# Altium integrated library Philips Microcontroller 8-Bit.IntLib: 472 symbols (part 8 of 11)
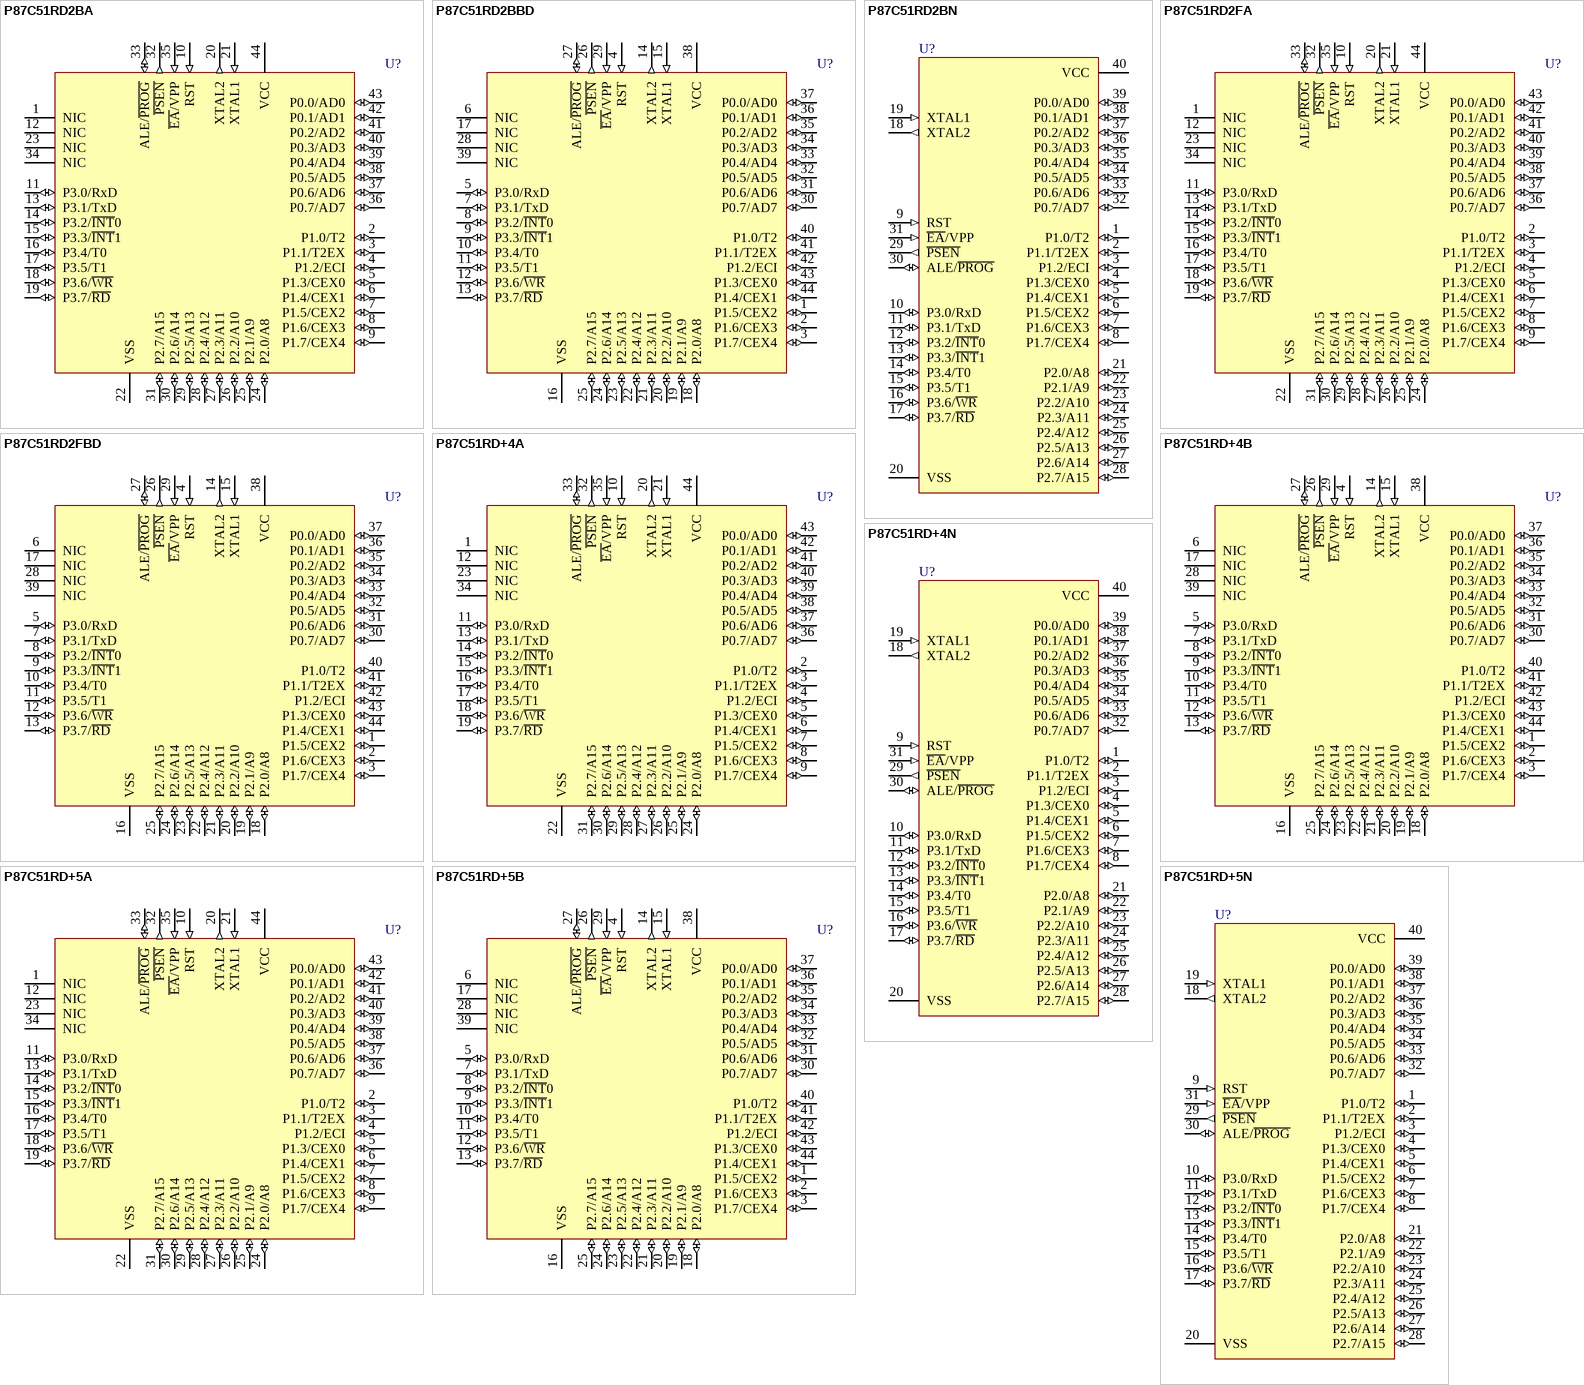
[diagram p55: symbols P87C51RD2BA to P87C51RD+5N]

## P87C51RD2FBD
designator U?
80C51 8-Bit Microcontroller Family: 64 kB OTP with 1 kB RAM, 2.7 to 5.5 V, Low Power, High Speed
footprint SOT389-1_N (Thin QFP, 44-Leads, Body 10x10mm, Pitch 0.8mm, IPC Medium Density)
footprint SOT389-1_L (Thin QFP, 44-Leads, Body 10x10mm, Pitch 0.8mm, IPC High Density)
footprint SOT389-1_M (Thin QFP, 44-Leads, Body 10x10mm, Pitch 0.8mm, IPC Low Density)
pins: 1 P1.5/CEX2 (io), 2 P1.6/CEX3 (io), 3 P1.7/CEX4 (io), 4 RST (in), 5 P3.0/RxD (io), 6 NIC, 7 P3.1/TxD (io), 8 P3.2/~{INT}0 (io), 9 P3.3/~{INT}1 (io), 10 P3.4/T0 (io), 11 P3.5/T1 (io), 12 P3.6/~{WR} (io), 13 P3.7/~{RD} (io), 14 XTAL2 (out), 15 XTAL1 (in), 16 VSS (power), 17 NIC, 18 P2.0/A8 (io), 19 P2.1/A9 (io), 20 P2.2/A10 (io), 21 P2.3/A11 (io), 22 P2.4/A12 (io), 23 P2.5/A13 (io), 24 P2.6/A14 (io), 25 P2.7/A15 (io), 26 ~{PSEN} (out), 27 ALE/~{PROG} (io), 28 NIC, 29 ~{EA}/VPP (in), 30 P0.7/AD7 (io), 31 P0.6/AD6 (io), 32 P0.5/AD5 (io), 33 P0.4/AD4 (io), 34 P0.3/AD3 (io), 35 P0.2/AD2 (io), 36 P0.1/AD1 (io), 37 P0.0/AD0 (io), 38 VCC (power), 39 NIC, 40 P1.0/T2 (io), 41 P1.1/T2EX (io), 42 P1.2/ECI (io), 43 P1.3/CEX0 (io), 44 P1.4/CEX1 (io)

## P87C51RD+4A
designator U?
80C51 8-Bit Microcontroller Family: 1 kB RAM, 64 kB OTP, 2.7V-5.5V, Low Power, High Speed
footprint SOT187-2_N (Leaded Chip Carrier, 44-Leads, Body 16.6x16.6mm, Pitch 1.27mm, IPC Medium Density)
footprint SOT187-2_L (Leaded Chip Carrier, 44-Leads, Body 16.6x16.6mm, Pitch 1.27mm, IPC High Density)
footprint SOT187-2_M (Leaded Chip Carrier, 44-Leads, Body 16.6x16.6mm, Pitch 1.27mm, IPC Low Density)
pins: 1 NIC, 2 P1.0/T2 (io), 3 P1.1/T2EX (io), 4 P1.2/ECI (io), 5 P1.3/CEX0 (io), 6 P1.4/CEX1 (io), 7 P1.5/CEX2 (io), 8 P1.6/CEX3 (io), 9 P1.7/CEX4 (io), 10 RST (in), 11 P3.0/RxD (io), 12 NIC, 13 P3.1/TxD (io), 14 P3.2/~{INT}0 (io), 15 P3.3/~{INT}1 (io), 16 P3.4/T0 (io), 17 P3.5/T1 (io), 18 P3.6/~{WR} (io), 19 P3.7/~{RD} (io), 20 XTAL2 (out), 21 XTAL1 (in), 22 VSS (power), 23 NIC, 24 P2.0/A8 (io), 25 P2.1/A9 (io), 26 P2.2/A10 (io), 27 P2.3/A11 (io), 28 P2.4/A12 (io), 29 P2.5/A13 (io), 30 P2.6/A14 (io), 31 P2.7/A15 (io), 32 ~{PSEN} (out), 33 ALE/~{PROG} (io), 34 NIC, 35 ~{EA}/VPP (in), 36 P0.7/AD7 (io), 37 P0.6/AD6 (io), 38 P0.5/AD5 (io), 39 P0.4/AD4 (io), 40 P0.3/AD3 (io), 41 P0.2/AD2 (io), 42 P0.1/AD1 (io), 43 P0.0/AD0 (io), 44 VCC (power)

## P87C51RD+4B
designator U?
80C51 8-Bit Microcontroller Family: 1 kB RAM, 64 kB OTP, 2.7V-5.5V, Low Power, High Speed
footprint SOT307-2_N (QFP, 44-Leads, Body 10x10mm, Pitch 0.8mm, IPC Medium Density)
footprint SOT307-2_L (QFP, 44-Leads, Body 10x10mm, Pitch 0.8mm, IPC High Density)
footprint SOT307-2_M (QFP, 44-Leads, Body 10x10mm, Pitch 0.8mm, IPC Low Density)
pins: 1 P1.5/CEX2 (io), 2 P1.6/CEX3 (io), 3 P1.7/CEX4 (io), 4 RST (in), 5 P3.0/RxD (io), 6 NIC, 7 P3.1/TxD (io), 8 P3.2/~{INT}0 (io), 9 P3.3/~{INT}1 (io), 10 P3.4/T0 (io), 11 P3.5/T1 (io), 12 P3.6/~{WR} (io), 13 P3.7/~{RD} (io), 14 XTAL2 (out), 15 XTAL1 (in), 16 VSS (power), 17 NIC, 18 P2.0/A8 (io), 19 P2.1/A9 (io), 20 P2.2/A10 (io), 21 P2.3/A11 (io), 22 P2.4/A12 (io), 23 P2.5/A13 (io), 24 P2.6/A14 (io), 25 P2.7/A15 (io), 26 ~{PSEN} (out), 27 ALE/~{PROG} (io), 28 NIC, 29 ~{EA}/VPP (in), 30 P0.7/AD7 (io), 31 P0.6/AD6 (io), 32 P0.5/AD5 (io), 33 P0.4/AD4 (io), 34 P0.3/AD3 (io), 35 P0.2/AD2 (io), 36 P0.1/AD1 (io), 37 P0.0/AD0 (io), 38 VCC (power), 39 NIC, 40 P1.0/T2 (io), 41 P1.1/T2EX (io), 42 P1.2/ECI (io), 43 P1.3/CEX0 (io), 44 P1.4/CEX1 (io)

## P87C51RD+4N
designator U?
80C51 8-Bit Microcontroller Family: 1 kB RAM, 64 kB OTP, 2.7V-5.5V, Low Power, High Speed
footprint SOT129-1 (DIP, Plastic; 40 Leads; Row Spacing 15.24 mm; Pitch 2.54 mm)
pins: 1 P1.0/T2 (io), 2 P1.1/T2EX (io), 3 P1.2/ECI (io), 4 P1.3/CEX0 (io), 5 P1.4/CEX1 (io), 6 P1.5/CEX2 (io), 7 P1.6/CEX3 (io), 8 P1.7/CEX4 (io), 9 RST (in), 10 P3.0/RxD (io), 11 P3.1/TxD (io), 12 P3.2/~{INT}0 (io), 13 P3.3/~{INT}1 (io), 14 P3.4/T0 (io), 15 P3.5/T1 (io), 16 P3.6/~{WR} (io), 17 P3.7/~{RD} (io), 18 XTAL2 (out), 19 XTAL1 (in), 20 VSS (power), 21 P2.0/A8 (io), 22 P2.1/A9 (io), 23 P2.2/A10 (io), 24 P2.3/A11 (io), 25 P2.4/A12 (io), 26 P2.5/A13 (io), 27 P2.6/A14 (io), 28 P2.7/A15 (io), 29 ~{PSEN} (out), 30 ALE/~{PROG} (io), 31 ~{EA}/VPP (in), 32 P0.7/AD7 (io), 33 P0.6/AD6 (io), 34 P0.5/AD5 (io), 35 P0.4/AD4 (io), 36 P0.3/AD3 (io), 37 P0.2/AD2 (io), 38 P0.1/AD1 (io), 39 P0.0/AD0 (io), 40 VCC (power)

## P87C51RD+5A
designator U?
80C51 8-Bit Microcontroller Family: 1 kB RAM, 64 kB OTP, 2.7V-5.5V, Low Power, High Speed
footprint SOT187-2_N (Leaded Chip Carrier, 44-Leads, Body 16.6x16.6mm, Pitch 1.27mm, IPC Medium Density)
footprint SOT187-2_L (Leaded Chip Carrier, 44-Leads, Body 16.6x16.6mm, Pitch 1.27mm, IPC High Density)
footprint SOT187-2_M (Leaded Chip Carrier, 44-Leads, Body 16.6x16.6mm, Pitch 1.27mm, IPC Low Density)
pins: 1 NIC, 2 P1.0/T2 (io), 3 P1.1/T2EX (io), 4 P1.2/ECI (io), 5 P1.3/CEX0 (io), 6 P1.4/CEX1 (io), 7 P1.5/CEX2 (io), 8 P1.6/CEX3 (io), 9 P1.7/CEX4 (io), 10 RST (in), 11 P3.0/RxD (io), 12 NIC, 13 P3.1/TxD (io), 14 P3.2/~{INT}0 (io), 15 P3.3/~{INT}1 (io), 16 P3.4/T0 (io), 17 P3.5/T1 (io), 18 P3.6/~{WR} (io), 19 P3.7/~{RD} (io), 20 XTAL2 (out), 21 XTAL1 (in), 22 VSS (power), 23 NIC, 24 P2.0/A8 (io), 25 P2.1/A9 (io), 26 P2.2/A10 (io), 27 P2.3/A11 (io), 28 P2.4/A12 (io), 29 P2.5/A13 (io), 30 P2.6/A14 (io), 31 P2.7/A15 (io), 32 ~{PSEN} (out), 33 ALE/~{PROG} (io), 34 NIC, 35 ~{EA}/VPP (in), 36 P0.7/AD7 (io), 37 P0.6/AD6 (io), 38 P0.5/AD5 (io), 39 P0.4/AD4 (io), 40 P0.3/AD3 (io), 41 P0.2/AD2 (io), 42 P0.1/AD1 (io), 43 P0.0/AD0 (io), 44 VCC (power)

## P87C51RD+5B
designator U?
80C51 8-Bit Microcontroller Family: 1 kB RAM, 64 kB OTP, 2.7V-5.5V, Low Power, High Speed
footprint SOT307-2_N (QFP, 44-Leads, Body 10x10mm, Pitch 0.8mm, IPC Medium Density)
footprint SOT307-2_L (QFP, 44-Leads, Body 10x10mm, Pitch 0.8mm, IPC High Density)
footprint SOT307-2_M (QFP, 44-Leads, Body 10x10mm, Pitch 0.8mm, IPC Low Density)
pins: 1 P1.5/CEX2 (io), 2 P1.6/CEX3 (io), 3 P1.7/CEX4 (io), 4 RST (in), 5 P3.0/RxD (io), 6 NIC, 7 P3.1/TxD (io), 8 P3.2/~{INT}0 (io), 9 P3.3/~{INT}1 (io), 10 P3.4/T0 (io), 11 P3.5/T1 (io), 12 P3.6/~{WR} (io), 13 P3.7/~{RD} (io), 14 XTAL2 (out), 15 XTAL1 (in), 16 VSS (power), 17 NIC, 18 P2.0/A8 (io), 19 P2.1/A9 (io), 20 P2.2/A10 (io), 21 P2.3/A11 (io), 22 P2.4/A12 (io), 23 P2.5/A13 (io), 24 P2.6/A14 (io), 25 P2.7/A15 (io), 26 ~{PSEN} (out), 27 ALE/~{PROG} (io), 28 NIC, 29 ~{EA}/VPP (in), 30 P0.7/AD7 (io), 31 P0.6/AD6 (io), 32 P0.5/AD5 (io), 33 P0.4/AD4 (io), 34 P0.3/AD3 (io), 35 P0.2/AD2 (io), 36 P0.1/AD1 (io), 37 P0.0/AD0 (io), 38 VCC (power), 39 NIC, 40 P1.0/T2 (io), 41 P1.1/T2EX (io), 42 P1.2/ECI (io), 43 P1.3/CEX0 (io), 44 P1.4/CEX1 (io)

## P87C51RD+5N
designator U?
80C51 8-Bit Microcontroller Family: 1 kB RAM, 64 kB OTP, 2.7V-5.5V, Low Power, High Speed
footprint SOT129-1 (DIP, Plastic; 40 Leads; Row Spacing 15.24 mm; Pitch 2.54 mm)
pins: 1 P1.0/T2 (io), 2 P1.1/T2EX (io), 3 P1.2/ECI (io), 4 P1.3/CEX0 (io), 5 P1.4/CEX1 (io), 6 P1.5/CEX2 (io), 7 P1.6/CEX3 (io), 8 P1.7/CEX4 (io), 9 RST (in), 10 P3.0/RxD (io), 11 P3.1/TxD (io), 12 P3.2/~{INT}0 (io), 13 P3.3/~{INT}1 (io), 14 P3.4/T0 (io), 15 P3.5/T1 (io), 16 P3.6/~{WR} (io), 17 P3.7/~{RD} (io), 18 XTAL2 (out), 19 XTAL1 (in), 20 VSS (power), 21 P2.0/A8 (io), 22 P2.1/A9 (io), 23 P2.2/A10 (io), 24 P2.3/A11 (io), 25 P2.4/A12 (io), 26 P2.5/A13 (io), 27 P2.6/A14 (io), 28 P2.7/A15 (io), 29 ~{PSEN} (out), 30 ALE/~{PROG} (io), 31 ~{EA}/VPP (in), 32 P0.7/AD7 (io), 33 P0.6/AD6 (io), 34 P0.5/AD5 (io), 35 P0.4/AD4 (io), 36 P0.3/AD3 (io), 37 P0.2/AD2 (io), 38 P0.1/AD1 (io), 39 P0.0/AD0 (io), 40 VCC (power)

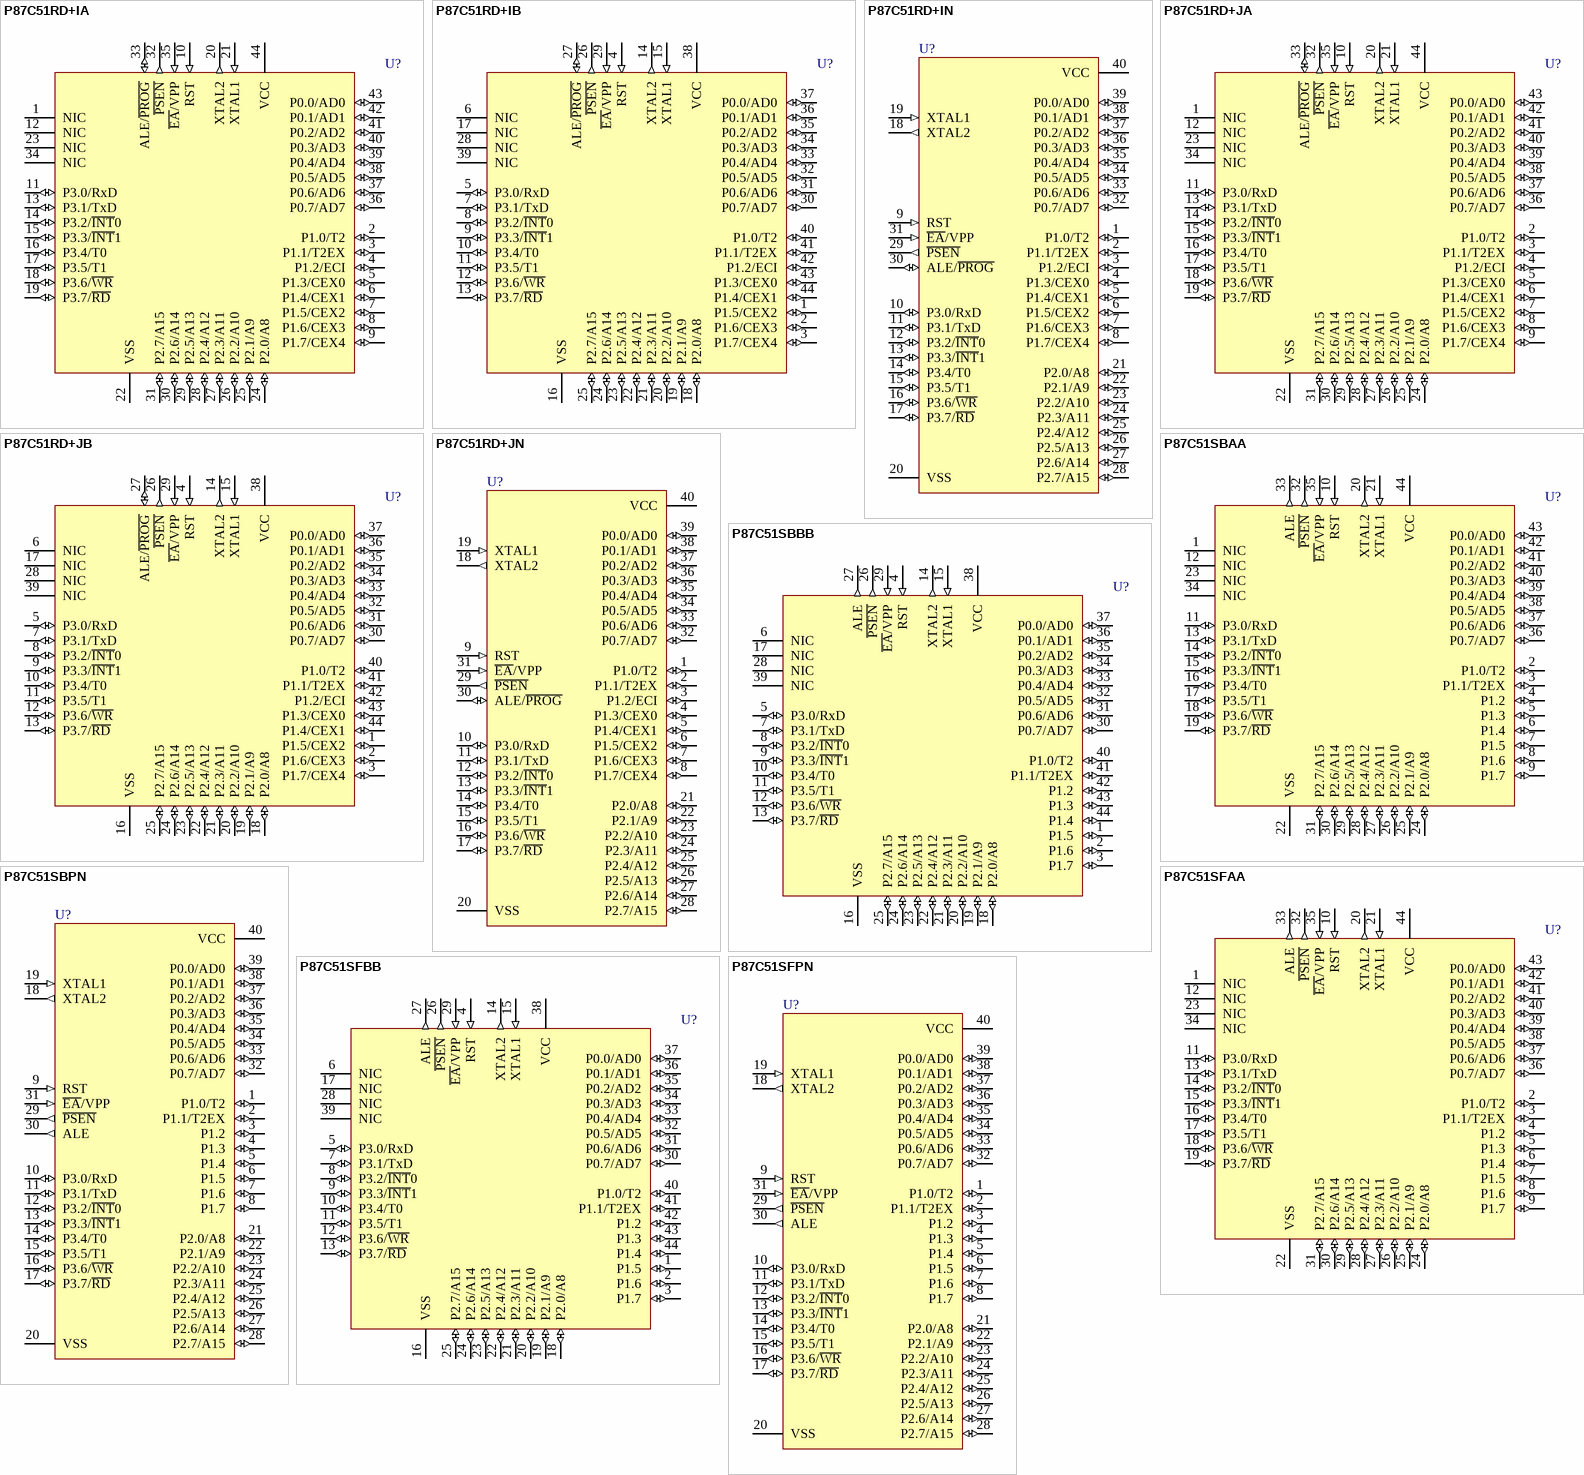
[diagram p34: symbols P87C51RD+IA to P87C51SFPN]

## P87C51RD+IA
designator U?
80C51 8-Bit Microcontroller Family: 1 kB RAM, 64 kB OTP, 5V, Low Power, High Speed
footprint SOT187-2_N (Leaded Chip Carrier, 44-Leads, Body 16.6x16.6mm, Pitch 1.27mm, IPC Medium Density)
footprint SOT187-2_L (Leaded Chip Carrier, 44-Leads, Body 16.6x16.6mm, Pitch 1.27mm, IPC High Density)
footprint SOT187-2_M (Leaded Chip Carrier, 44-Leads, Body 16.6x16.6mm, Pitch 1.27mm, IPC Low Density)
pins: 1 NIC, 2 P1.0/T2 (io), 3 P1.1/T2EX (io), 4 P1.2/ECI (io), 5 P1.3/CEX0 (io), 6 P1.4/CEX1 (io), 7 P1.5/CEX2 (io), 8 P1.6/CEX3 (io), 9 P1.7/CEX4 (io), 10 RST (in), 11 P3.0/RxD (io), 12 NIC, 13 P3.1/TxD (io), 14 P3.2/~{INT}0 (io), 15 P3.3/~{INT}1 (io), 16 P3.4/T0 (io), 17 P3.5/T1 (io), 18 P3.6/~{WR} (io), 19 P3.7/~{RD} (io), 20 XTAL2 (out), 21 XTAL1 (in), 22 VSS (power), 23 NIC, 24 P2.0/A8 (io), 25 P2.1/A9 (io), 26 P2.2/A10 (io), 27 P2.3/A11 (io), 28 P2.4/A12 (io), 29 P2.5/A13 (io), 30 P2.6/A14 (io), 31 P2.7/A15 (io), 32 ~{PSEN} (out), 33 ALE/~{PROG} (io), 34 NIC, 35 ~{EA}/VPP (in), 36 P0.7/AD7 (io), 37 P0.6/AD6 (io), 38 P0.5/AD5 (io), 39 P0.4/AD4 (io), 40 P0.3/AD3 (io), 41 P0.2/AD2 (io), 42 P0.1/AD1 (io), 43 P0.0/AD0 (io), 44 VCC (power)

## P87C51RD+IB
designator U?
80C51 8-Bit Microcontroller Family: 1 kB RAM, 64 kB OTP, 5V, Low Power, High Speed
footprint SOT307-2_N (QFP, 44-Leads, Body 10x10mm, Pitch 0.8mm, IPC Medium Density)
footprint SOT307-2_L (QFP, 44-Leads, Body 10x10mm, Pitch 0.8mm, IPC High Density)
footprint SOT307-2_M (QFP, 44-Leads, Body 10x10mm, Pitch 0.8mm, IPC Low Density)
pins: 1 P1.5/CEX2 (io), 2 P1.6/CEX3 (io), 3 P1.7/CEX4 (io), 4 RST (in), 5 P3.0/RxD (io), 6 NIC, 7 P3.1/TxD (io), 8 P3.2/~{INT}0 (io), 9 P3.3/~{INT}1 (io), 10 P3.4/T0 (io), 11 P3.5/T1 (io), 12 P3.6/~{WR} (io), 13 P3.7/~{RD} (io), 14 XTAL2 (out), 15 XTAL1 (in), 16 VSS (power), 17 NIC, 18 P2.0/A8 (io), 19 P2.1/A9 (io), 20 P2.2/A10 (io), 21 P2.3/A11 (io), 22 P2.4/A12 (io), 23 P2.5/A13 (io), 24 P2.6/A14 (io), 25 P2.7/A15 (io), 26 ~{PSEN} (out), 27 ALE/~{PROG} (io), 28 NIC, 29 ~{EA}/VPP (in), 30 P0.7/AD7 (io), 31 P0.6/AD6 (io), 32 P0.5/AD5 (io), 33 P0.4/AD4 (io), 34 P0.3/AD3 (io), 35 P0.2/AD2 (io), 36 P0.1/AD1 (io), 37 P0.0/AD0 (io), 38 VCC (power), 39 NIC, 40 P1.0/T2 (io), 41 P1.1/T2EX (io), 42 P1.2/ECI (io), 43 P1.3/CEX0 (io), 44 P1.4/CEX1 (io)

## P87C51RD+IN
designator U?
80C51 8-Bit Microcontroller Family: 1 kB RAM, 64 kB OTP, 5V, Low Power, High Speed
footprint SOT129-1 (DIP, Plastic; 40 Leads; Row Spacing 15.24 mm; Pitch 2.54 mm)
pins: 1 P1.0/T2 (io), 2 P1.1/T2EX (io), 3 P1.2/ECI (io), 4 P1.3/CEX0 (io), 5 P1.4/CEX1 (io), 6 P1.5/CEX2 (io), 7 P1.6/CEX3 (io), 8 P1.7/CEX4 (io), 9 RST (in), 10 P3.0/RxD (io), 11 P3.1/TxD (io), 12 P3.2/~{INT}0 (io), 13 P3.3/~{INT}1 (io), 14 P3.4/T0 (io), 15 P3.5/T1 (io), 16 P3.6/~{WR} (io), 17 P3.7/~{RD} (io), 18 XTAL2 (out), 19 XTAL1 (in), 20 VSS (power), 21 P2.0/A8 (io), 22 P2.1/A9 (io), 23 P2.2/A10 (io), 24 P2.3/A11 (io), 25 P2.4/A12 (io), 26 P2.5/A13 (io), 27 P2.6/A14 (io), 28 P2.7/A15 (io), 29 ~{PSEN} (out), 30 ALE/~{PROG} (io), 31 ~{EA}/VPP (in), 32 P0.7/AD7 (io), 33 P0.6/AD6 (io), 34 P0.5/AD5 (io), 35 P0.4/AD4 (io), 36 P0.3/AD3 (io), 37 P0.2/AD2 (io), 38 P0.1/AD1 (io), 39 P0.0/AD0 (io), 40 VCC (power)

## P87C51RD+JA
designator U?
80C51 8-Bit Microcontroller Family: 1 kB RAM, 64 kB OTP, 5V, Low Power, High Speed
footprint SOT187-2_N (Leaded Chip Carrier, 44-Leads, Body 16.6x16.6mm, Pitch 1.27mm, IPC Medium Density)
footprint SOT187-2_L (Leaded Chip Carrier, 44-Leads, Body 16.6x16.6mm, Pitch 1.27mm, IPC High Density)
footprint SOT187-2_M (Leaded Chip Carrier, 44-Leads, Body 16.6x16.6mm, Pitch 1.27mm, IPC Low Density)
pins: 1 NIC, 2 P1.0/T2 (io), 3 P1.1/T2EX (io), 4 P1.2/ECI (io), 5 P1.3/CEX0 (io), 6 P1.4/CEX1 (io), 7 P1.5/CEX2 (io), 8 P1.6/CEX3 (io), 9 P1.7/CEX4 (io), 10 RST (in), 11 P3.0/RxD (io), 12 NIC, 13 P3.1/TxD (io), 14 P3.2/~{INT}0 (io), 15 P3.3/~{INT}1 (io), 16 P3.4/T0 (io), 17 P3.5/T1 (io), 18 P3.6/~{WR} (io), 19 P3.7/~{RD} (io), 20 XTAL2 (out), 21 XTAL1 (in), 22 VSS (power), 23 NIC, 24 P2.0/A8 (io), 25 P2.1/A9 (io), 26 P2.2/A10 (io), 27 P2.3/A11 (io), 28 P2.4/A12 (io), 29 P2.5/A13 (io), 30 P2.6/A14 (io), 31 P2.7/A15 (io), 32 ~{PSEN} (out), 33 ALE/~{PROG} (io), 34 NIC, 35 ~{EA}/VPP (in), 36 P0.7/AD7 (io), 37 P0.6/AD6 (io), 38 P0.5/AD5 (io), 39 P0.4/AD4 (io), 40 P0.3/AD3 (io), 41 P0.2/AD2 (io), 42 P0.1/AD1 (io), 43 P0.0/AD0 (io), 44 VCC (power)

## P87C51RD+JB
designator U?
80C51 8-Bit Microcontroller Family: 1 kB RAM, 64 kB OTP, 5V, Low Power, High Speed
footprint SOT307-2_N (QFP, 44-Leads, Body 10x10mm, Pitch 0.8mm, IPC Medium Density)
footprint SOT307-2_L (QFP, 44-Leads, Body 10x10mm, Pitch 0.8mm, IPC High Density)
footprint SOT307-2_M (QFP, 44-Leads, Body 10x10mm, Pitch 0.8mm, IPC Low Density)
pins: 1 P1.5/CEX2 (io), 2 P1.6/CEX3 (io), 3 P1.7/CEX4 (io), 4 RST (in), 5 P3.0/RxD (io), 6 NIC, 7 P3.1/TxD (io), 8 P3.2/~{INT}0 (io), 9 P3.3/~{INT}1 (io), 10 P3.4/T0 (io), 11 P3.5/T1 (io), 12 P3.6/~{WR} (io), 13 P3.7/~{RD} (io), 14 XTAL2 (out), 15 XTAL1 (in), 16 VSS (power), 17 NIC, 18 P2.0/A8 (io), 19 P2.1/A9 (io), 20 P2.2/A10 (io), 21 P2.3/A11 (io), 22 P2.4/A12 (io), 23 P2.5/A13 (io), 24 P2.6/A14 (io), 25 P2.7/A15 (io), 26 ~{PSEN} (out), 27 ALE/~{PROG} (io), 28 NIC, 29 ~{EA}/VPP (in), 30 P0.7/AD7 (io), 31 P0.6/AD6 (io), 32 P0.5/AD5 (io), 33 P0.4/AD4 (io), 34 P0.3/AD3 (io), 35 P0.2/AD2 (io), 36 P0.1/AD1 (io), 37 P0.0/AD0 (io), 38 VCC (power), 39 NIC, 40 P1.0/T2 (io), 41 P1.1/T2EX (io), 42 P1.2/ECI (io), 43 P1.3/CEX0 (io), 44 P1.4/CEX1 (io)

## P87C51RD+JN
designator U?
80C51 8-Bit Microcontroller Family: 1 kB RAM, 64 kB OTP, 5V, Low Power, High Speed
footprint SOT129-1 (DIP, Plastic; 40 Leads; Row Spacing 15.24 mm; Pitch 2.54 mm)
pins: 1 P1.0/T2 (io), 2 P1.1/T2EX (io), 3 P1.2/ECI (io), 4 P1.3/CEX0 (io), 5 P1.4/CEX1 (io), 6 P1.5/CEX2 (io), 7 P1.6/CEX3 (io), 8 P1.7/CEX4 (io), 9 RST (in), 10 P3.0/RxD (io), 11 P3.1/TxD (io), 12 P3.2/~{INT}0 (io), 13 P3.3/~{INT}1 (io), 14 P3.4/T0 (io), 15 P3.5/T1 (io), 16 P3.6/~{WR} (io), 17 P3.7/~{RD} (io), 18 XTAL2 (out), 19 XTAL1 (in), 20 VSS (power), 21 P2.0/A8 (io), 22 P2.1/A9 (io), 23 P2.2/A10 (io), 24 P2.3/A11 (io), 25 P2.4/A12 (io), 26 P2.5/A13 (io), 27 P2.6/A14 (io), 28 P2.7/A15 (io), 29 ~{PSEN} (out), 30 ALE/~{PROG} (io), 31 ~{EA}/VPP (in), 32 P0.7/AD7 (io), 33 P0.6/AD6 (io), 34 P0.5/AD5 (io), 35 P0.4/AD4 (io), 36 P0.3/AD3 (io), 37 P0.2/AD2 (io), 38 P0.1/AD1 (io), 39 P0.0/AD0 (io), 40 VCC (power)

## P87C51SBAA
designator U?
80C51 8-Bit Microcontroller Family: 128 B RAM, 4 kB OTP, 2.7V-5.5V, Low Power, High Speed
footprint SOT187-2_N (Leaded Chip Carrier, 44-Leads, Body 16.6x16.6mm, Pitch 1.27mm, IPC Medium Density)
footprint SOT187-2_L (Leaded Chip Carrier, 44-Leads, Body 16.6x16.6mm, Pitch 1.27mm, IPC High Density)
footprint SOT187-2_M (Leaded Chip Carrier, 44-Leads, Body 16.6x16.6mm, Pitch 1.27mm, IPC Low Density)
pins: 1 NIC, 2 P1.0/T2 (io), 3 P1.1/T2EX (io), 4 P1.2 (io), 5 P1.3 (io), 6 P1.4 (io), 7 P1.5 (io), 8 P1.6 (io), 9 P1.7 (io), 10 RST (in), 11 P3.0/RxD (io), 12 NIC, 13 P3.1/TxD (io), 14 P3.2/~{INT}0 (io), 15 P3.3/~{INT}1 (io), 16 P3.4/T0 (io), 17 P3.5/T1 (io), 18 P3.6/~{WR} (io), 19 P3.7/~{RD} (io), 20 XTAL2 (out), 21 XTAL1 (in), 22 VSS (power), 23 NIC, 24 P2.0/A8 (io), 25 P2.1/A9 (io), 26 P2.2/A10 (io), 27 P2.3/A11 (io), 28 P2.4/A12 (io), 29 P2.5/A13 (io), 30 P2.6/A14 (io), 31 P2.7/A15 (io), 32 ~{PSEN} (out), 33 ALE (out), 34 NIC, 35 ~{EA}/VPP (in), 36 P0.7/AD7 (io), 37 P0.6/AD6 (io), 38 P0.5/AD5 (io), 39 P0.4/AD4 (io), 40 P0.3/AD3 (io), 41 P0.2/AD2 (io), 42 P0.1/AD1 (io), 43 P0.0/AD0 (io), 44 VCC (power)

## P87C51SBBB
designator U?
80C51 8-Bit Microcontroller Family: 128 B RAM, 4 kB OTP, 2.7V-5.5V, Low Power, High Speed
footprint SOT307-2_N (QFP, 44-Leads, Body 10x10mm, Pitch 0.8mm, IPC Medium Density)
footprint SOT307-2_L (QFP, 44-Leads, Body 10x10mm, Pitch 0.8mm, IPC High Density)
footprint SOT307-2_M (QFP, 44-Leads, Body 10x10mm, Pitch 0.8mm, IPC Low Density)
pins: 1 P1.5 (io), 2 P1.6 (io), 3 P1.7 (io), 4 RST (in), 5 P3.0/RxD (io), 6 NIC, 7 P3.1/TxD (io), 8 P3.2/~{INT}0 (io), 9 P3.3/~{INT}1 (io), 10 P3.4/T0 (io), 11 P3.5/T1 (io), 12 P3.6/~{WR} (io), 13 P3.7/~{RD} (io), 14 XTAL2 (out), 15 XTAL1 (in), 16 VSS (power), 17 NIC, 18 P2.0/A8 (io), 19 P2.1/A9 (io), 20 P2.2/A10 (io), 21 P2.3/A11 (io), 22 P2.4/A12 (io), 23 P2.5/A13 (io), 24 P2.6/A14 (io), 25 P2.7/A15 (io), 26 ~{PSEN} (out), 27 ALE (out), 28 NIC, 29 ~{EA}/VPP (in), 30 P0.7/AD7 (io), 31 P0.6/AD6 (io), 32 P0.5/AD5 (io), 33 P0.4/AD4 (io), 34 P0.3/AD3 (io), 35 P0.2/AD2 (io), 36 P0.1/AD1 (io), 37 P0.0/AD0 (io), 38 VCC (power), 39 NIC, 40 P1.0/T2 (io), 41 P1.1/T2EX (io), 42 P1.2 (io), 43 P1.3 (io), 44 P1.4 (io)

## P87C51SBPN
designator U?
80C51 8-Bit Microcontroller Family: 128 B RAM, 4 kB OTP, 2.7V-5.5V, Low Power, High Speed
footprint SOT129-1 (DIP, Plastic; 40 Leads; Row Spacing 15.24 mm; Pitch 2.54 mm)
pins: 1 P1.0/T2 (io), 2 P1.1/T2EX (io), 3 P1.2 (io), 4 P1.3 (io), 5 P1.4 (io), 6 P1.5 (io), 7 P1.6 (io), 8 P1.7 (io), 9 RST (in), 10 P3.0/RxD (io), 11 P3.1/TxD (io), 12 P3.2/~{INT}0 (io), 13 P3.3/~{INT}1 (io), 14 P3.4/T0 (io), 15 P3.5/T1 (io), 16 P3.6/~{WR} (io), 17 P3.7/~{RD} (io), 18 XTAL2 (out), 19 XTAL1 (in), 20 VSS (power), 21 P2.0/A8 (io), 22 P2.1/A9 (io), 23 P2.2/A10 (io), 24 P2.3/A11 (io), 25 P2.4/A12 (io), 26 P2.5/A13 (io), 27 P2.6/A14 (io), 28 P2.7/A15 (io), 29 ~{PSEN} (out), 30 ALE (out), 31 ~{EA}/VPP (in), 32 P0.7/AD7 (io), 33 P0.6/AD6 (io), 34 P0.5/AD5 (io), 35 P0.4/AD4 (io), 36 P0.3/AD3 (io), 37 P0.2/AD2 (io), 38 P0.1/AD1 (io), 39 P0.0/AD0 (io), 40 VCC (power)

## P87C51SFAA
designator U?
80C51 8-Bit Microcontroller Family: 128 B RAM, 4 kB OTP, 2.7V-5.5V, Low Power, High Speed
footprint SOT187-2_N (Leaded Chip Carrier, 44-Leads, Body 16.6x16.6mm, Pitch 1.27mm, IPC Medium Density)
footprint SOT187-2_L (Leaded Chip Carrier, 44-Leads, Body 16.6x16.6mm, Pitch 1.27mm, IPC High Density)
footprint SOT187-2_M (Leaded Chip Carrier, 44-Leads, Body 16.6x16.6mm, Pitch 1.27mm, IPC Low Density)
pins: 1 NIC, 2 P1.0/T2 (io), 3 P1.1/T2EX (io), 4 P1.2 (io), 5 P1.3 (io), 6 P1.4 (io), 7 P1.5 (io), 8 P1.6 (io), 9 P1.7 (io), 10 RST (in), 11 P3.0/RxD (io), 12 NIC, 13 P3.1/TxD (io), 14 P3.2/~{INT}0 (io), 15 P3.3/~{INT}1 (io), 16 P3.4/T0 (io), 17 P3.5/T1 (io), 18 P3.6/~{WR} (io), 19 P3.7/~{RD} (io), 20 XTAL2 (out), 21 XTAL1 (in), 22 VSS (power), 23 NIC, 24 P2.0/A8 (io), 25 P2.1/A9 (io), 26 P2.2/A10 (io), 27 P2.3/A11 (io), 28 P2.4/A12 (io), 29 P2.5/A13 (io), 30 P2.6/A14 (io), 31 P2.7/A15 (io), 32 ~{PSEN} (out), 33 ALE (out), 34 NIC, 35 ~{EA}/VPP (in), 36 P0.7/AD7 (io), 37 P0.6/AD6 (io), 38 P0.5/AD5 (io), 39 P0.4/AD4 (io), 40 P0.3/AD3 (io), 41 P0.2/AD2 (io), 42 P0.1/AD1 (io), 43 P0.0/AD0 (io), 44 VCC (power)

## P87C51SFBB
designator U?
80C51 8-Bit Microcontroller Family: 128 B RAM, 4 kB OTP, 2.7V-5.5V, Low Power, High Speed
footprint SOT307-2_N (QFP, 44-Leads, Body 10x10mm, Pitch 0.8mm, IPC Medium Density)
footprint SOT307-2_L (QFP, 44-Leads, Body 10x10mm, Pitch 0.8mm, IPC High Density)
footprint SOT307-2_M (QFP, 44-Leads, Body 10x10mm, Pitch 0.8mm, IPC Low Density)
pins: 1 P1.5 (io), 2 P1.6 (io), 3 P1.7 (io), 4 RST (in), 5 P3.0/RxD (io), 6 NIC, 7 P3.1/TxD (io), 8 P3.2/~{INT}0 (io), 9 P3.3/~{INT}1 (io), 10 P3.4/T0 (io), 11 P3.5/T1 (io), 12 P3.6/~{WR} (io), 13 P3.7/~{RD} (io), 14 XTAL2 (out), 15 XTAL1 (in), 16 VSS (power), 17 NIC, 18 P2.0/A8 (io), 19 P2.1/A9 (io), 20 P2.2/A10 (io), 21 P2.3/A11 (io), 22 P2.4/A12 (io), 23 P2.5/A13 (io), 24 P2.6/A14 (io), 25 P2.7/A15 (io), 26 ~{PSEN} (out), 27 ALE (out), 28 NIC, 29 ~{EA}/VPP (in), 30 P0.7/AD7 (io), 31 P0.6/AD6 (io), 32 P0.5/AD5 (io), 33 P0.4/AD4 (io), 34 P0.3/AD3 (io), 35 P0.2/AD2 (io), 36 P0.1/AD1 (io), 37 P0.0/AD0 (io), 38 VCC (power), 39 NIC, 40 P1.0/T2 (io), 41 P1.1/T2EX (io), 42 P1.2 (io), 43 P1.3 (io), 44 P1.4 (io)

## P87C51SFPN
designator U?
80C51 8-Bit Microcontroller Family: 128 B RAM, 4 kB OTP, 2.7V-5.5V, Low Power, High Speed
footprint SOT129-1 (DIP, Plastic; 40 Leads; Row Spacing 15.24 mm; Pitch 2.54 mm)
pins: 1 P1.0/T2 (io), 2 P1.1/T2EX (io), 3 P1.2 (io), 4 P1.3 (io), 5 P1.4 (io), 6 P1.5 (io), 7 P1.6 (io), 8 P1.7 (io), 9 RST (in), 10 P3.0/RxD (io), 11 P3.1/TxD (io), 12 P3.2/~{INT}0 (io), 13 P3.3/~{INT}1 (io), 14 P3.4/T0 (io), 15 P3.5/T1 (io), 16 P3.6/~{WR} (io), 17 P3.7/~{RD} (io), 18 XTAL2 (out), 19 XTAL1 (in), 20 VSS (power), 21 P2.0/A8 (io), 22 P2.1/A9 (io), 23 P2.2/A10 (io), 24 P2.3/A11 (io), 25 P2.4/A12 (io), 26 P2.5/A13 (io), 27 P2.6/A14 (io), 28 P2.7/A15 (io), 29 ~{PSEN} (out), 30 ALE (out), 31 ~{EA}/VPP (in), 32 P0.7/AD7 (io), 33 P0.6/AD6 (io), 34 P0.5/AD5 (io), 35 P0.4/AD4 (io), 36 P0.3/AD3 (io), 37 P0.2/AD2 (io), 38 P0.1/AD1 (io), 39 P0.0/AD0 (io), 40 VCC (power)

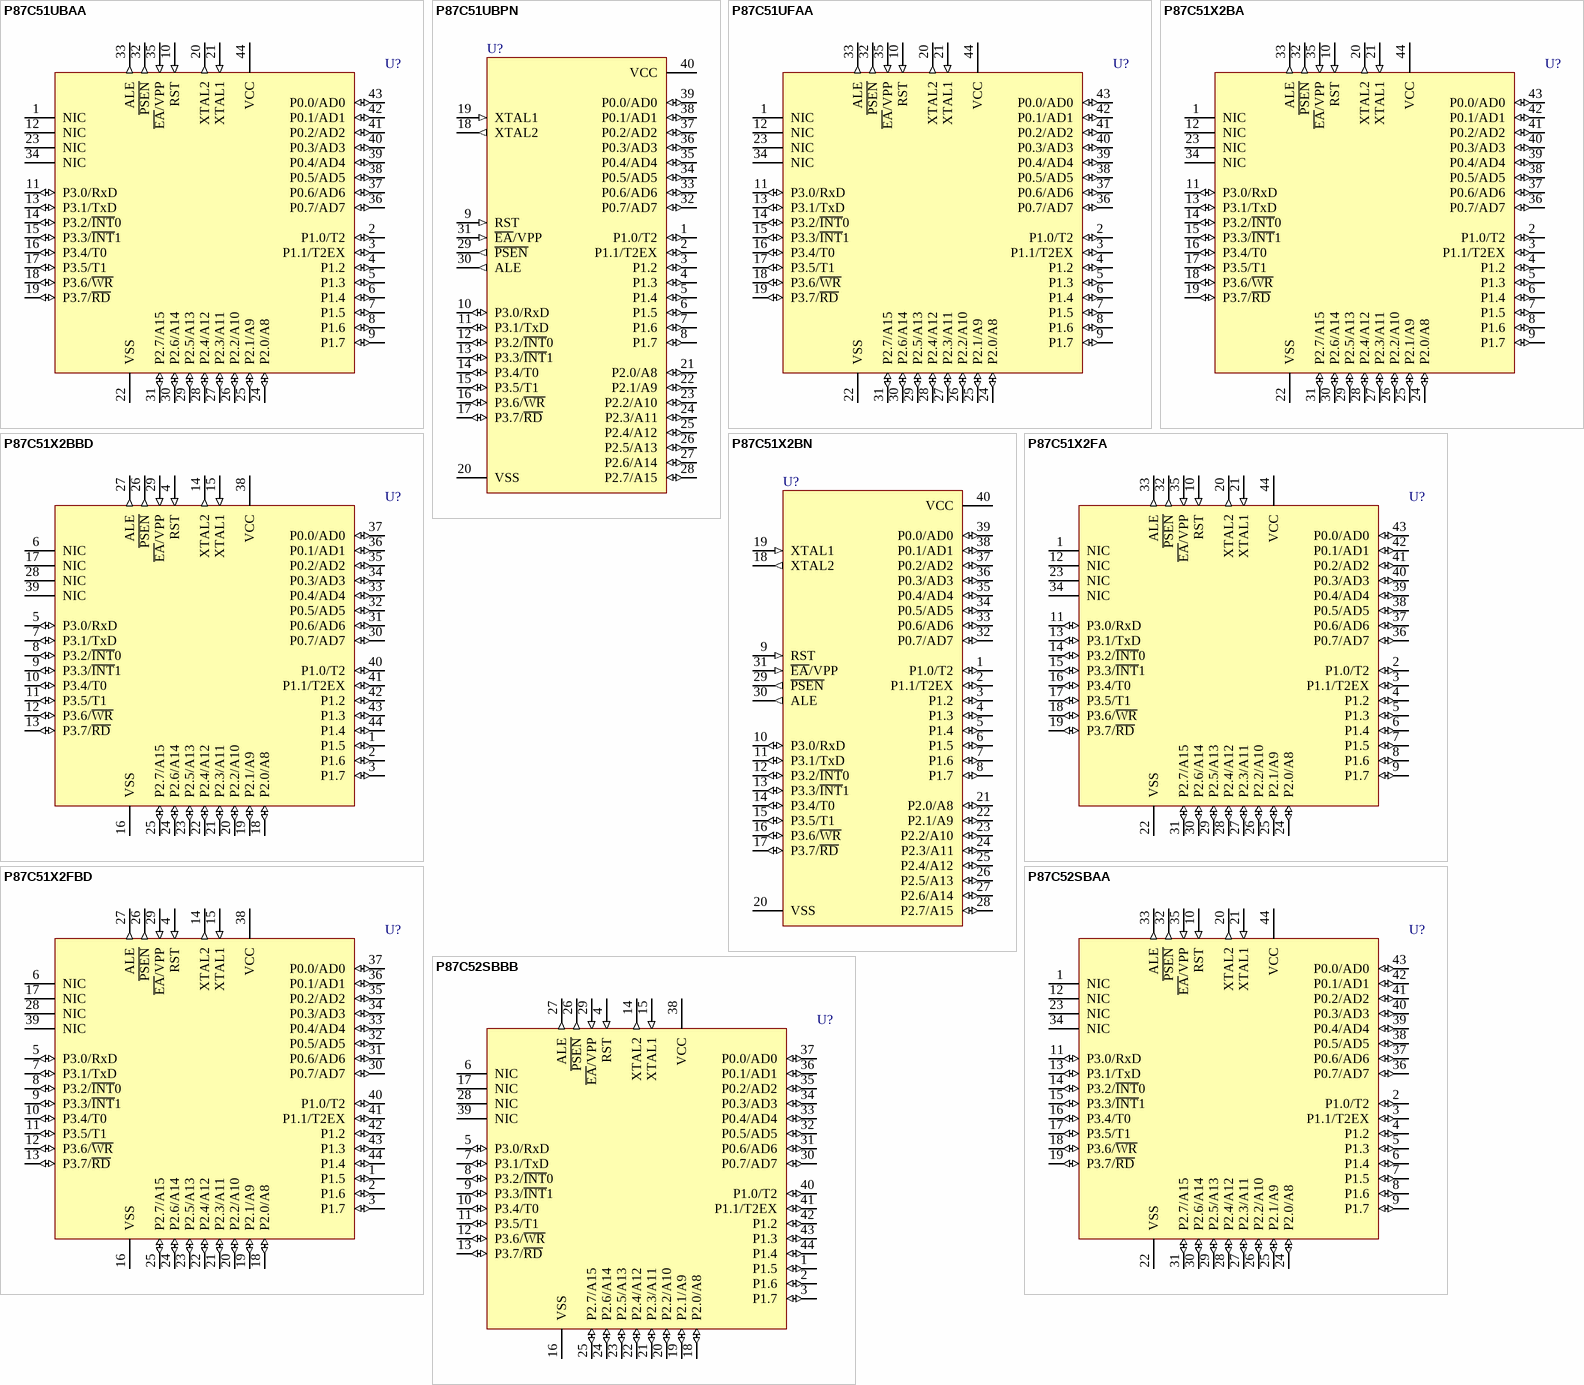
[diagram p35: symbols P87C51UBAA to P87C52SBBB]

## P87C51UBAA
designator U?
80C51 8-Bit Microcontroller Family: 128 B RAM, 4 kB OTP, 5V, Low Power, High Speed
footprint SOT187-2_N (Leaded Chip Carrier, 44-Leads, Body 16.6x16.6mm, Pitch 1.27mm, IPC Medium Density)
footprint SOT187-2_L (Leaded Chip Carrier, 44-Leads, Body 16.6x16.6mm, Pitch 1.27mm, IPC High Density)
footprint SOT187-2_M (Leaded Chip Carrier, 44-Leads, Body 16.6x16.6mm, Pitch 1.27mm, IPC Low Density)
pins: 1 NIC, 2 P1.0/T2 (io), 3 P1.1/T2EX (io), 4 P1.2 (io), 5 P1.3 (io), 6 P1.4 (io), 7 P1.5 (io), 8 P1.6 (io), 9 P1.7 (io), 10 RST (in), 11 P3.0/RxD (io), 12 NIC, 13 P3.1/TxD (io), 14 P3.2/~{INT}0 (io), 15 P3.3/~{INT}1 (io), 16 P3.4/T0 (io), 17 P3.5/T1 (io), 18 P3.6/~{WR} (io), 19 P3.7/~{RD} (io), 20 XTAL2 (out), 21 XTAL1 (in), 22 VSS (power), 23 NIC, 24 P2.0/A8 (io), 25 P2.1/A9 (io), 26 P2.2/A10 (io), 27 P2.3/A11 (io), 28 P2.4/A12 (io), 29 P2.5/A13 (io), 30 P2.6/A14 (io), 31 P2.7/A15 (io), 32 ~{PSEN} (out), 33 ALE (out), 34 NIC, 35 ~{EA}/VPP (in), 36 P0.7/AD7 (io), 37 P0.6/AD6 (io), 38 P0.5/AD5 (io), 39 P0.4/AD4 (io), 40 P0.3/AD3 (io), 41 P0.2/AD2 (io), 42 P0.1/AD1 (io), 43 P0.0/AD0 (io), 44 VCC (power)

## P87C51UBPN
designator U?
80C51 8-Bit Microcontroller Family: 128 B RAM, 4 kB OTP, 5V, Low Power, High Speed
footprint SOT129-1 (DIP, Plastic; 40 Leads; Row Spacing 15.24 mm; Pitch 2.54 mm)
pins: 1 P1.0/T2 (io), 2 P1.1/T2EX (io), 3 P1.2 (io), 4 P1.3 (io), 5 P1.4 (io), 6 P1.5 (io), 7 P1.6 (io), 8 P1.7 (io), 9 RST (in), 10 P3.0/RxD (io), 11 P3.1/TxD (io), 12 P3.2/~{INT}0 (io), 13 P3.3/~{INT}1 (io), 14 P3.4/T0 (io), 15 P3.5/T1 (io), 16 P3.6/~{WR} (io), 17 P3.7/~{RD} (io), 18 XTAL2 (out), 19 XTAL1 (in), 20 VSS (power), 21 P2.0/A8 (io), 22 P2.1/A9 (io), 23 P2.2/A10 (io), 24 P2.3/A11 (io), 25 P2.4/A12 (io), 26 P2.5/A13 (io), 27 P2.6/A14 (io), 28 P2.7/A15 (io), 29 ~{PSEN} (out), 30 ALE (out), 31 ~{EA}/VPP (in), 32 P0.7/AD7 (io), 33 P0.6/AD6 (io), 34 P0.5/AD5 (io), 35 P0.4/AD4 (io), 36 P0.3/AD3 (io), 37 P0.2/AD2 (io), 38 P0.1/AD1 (io), 39 P0.0/AD0 (io), 40 VCC (power)

## P87C51UFAA
designator U?
80C51 8-Bit Microcontroller Family: 128 B RAM, 4 kB OTP, 5V, Low Power, High Speed
footprint SOT187-2_N (Leaded Chip Carrier, 44-Leads, Body 16.6x16.6mm, Pitch 1.27mm, IPC Medium Density)
footprint SOT187-2_L (Leaded Chip Carrier, 44-Leads, Body 16.6x16.6mm, Pitch 1.27mm, IPC High Density)
footprint SOT187-2_M (Leaded Chip Carrier, 44-Leads, Body 16.6x16.6mm, Pitch 1.27mm, IPC Low Density)
pins: 1 NIC, 2 P1.0/T2 (io), 3 P1.1/T2EX (io), 4 P1.2 (io), 5 P1.3 (io), 6 P1.4 (io), 7 P1.5 (io), 8 P1.6 (io), 9 P1.7 (io), 10 RST (in), 11 P3.0/RxD (io), 12 NIC, 13 P3.1/TxD (io), 14 P3.2/~{INT}0 (io), 15 P3.3/~{INT}1 (io), 16 P3.4/T0 (io), 17 P3.5/T1 (io), 18 P3.6/~{WR} (io), 19 P3.7/~{RD} (io), 20 XTAL2 (out), 21 XTAL1 (in), 22 VSS (power), 23 NIC, 24 P2.0/A8 (io), 25 P2.1/A9 (io), 26 P2.2/A10 (io), 27 P2.3/A11 (io), 28 P2.4/A12 (io), 29 P2.5/A13 (io), 30 P2.6/A14 (io), 31 P2.7/A15 (io), 32 ~{PSEN} (out), 33 ALE (out), 34 NIC, 35 ~{EA}/VPP (in), 36 P0.7/AD7 (io), 37 P0.6/AD6 (io), 38 P0.5/AD5 (io), 39 P0.4/AD4 (io), 40 P0.3/AD3 (io), 41 P0.2/AD2 (io), 42 P0.1/AD1 (io), 43 P0.0/AD0 (io), 44 VCC (power)

## P87C51X2BA
designator U?
80C51 8-Bit Microcontroller Family: 128 B RAM, 4 kB OTP, 2.7 to 5.5 V, Low Power, High Speed
footprint SOT187-2_N (Leaded Chip Carrier, 44-Leads, Body 16.6x16.6mm, Pitch 1.27mm, IPC Medium Density)
footprint SOT187-2_L (Leaded Chip Carrier, 44-Leads, Body 16.6x16.6mm, Pitch 1.27mm, IPC High Density)
footprint SOT187-2_M (Leaded Chip Carrier, 44-Leads, Body 16.6x16.6mm, Pitch 1.27mm, IPC Low Density)
pins: 1 NIC, 2 P1.0/T2 (io), 3 P1.1/T2EX (io), 4 P1.2 (io), 5 P1.3 (io), 6 P1.4 (io), 7 P1.5 (io), 8 P1.6 (io), 9 P1.7 (io), 10 RST (in), 11 P3.0/RxD (io), 12 NIC, 13 P3.1/TxD (io), 14 P3.2/~{INT}0 (io), 15 P3.3/~{INT}1 (io), 16 P3.4/T0 (io), 17 P3.5/T1 (io), 18 P3.6/~{WR} (io), 19 P3.7/~{RD} (io), 20 XTAL2 (out), 21 XTAL1 (in), 22 VSS (power), 23 NIC, 24 P2.0/A8 (io), 25 P2.1/A9 (io), 26 P2.2/A10 (io), 27 P2.3/A11 (io), 28 P2.4/A12 (io), 29 P2.5/A13 (io), 30 P2.6/A14 (io), 31 P2.7/A15 (io), 32 ~{PSEN} (out), 33 ALE (out), 34 NIC, 35 ~{EA}/VPP (in), 36 P0.7/AD7 (io), 37 P0.6/AD6 (io), 38 P0.5/AD5 (io), 39 P0.4/AD4 (io), 40 P0.3/AD3 (io), 41 P0.2/AD2 (io), 42 P0.1/AD1 (io), 43 P0.0/AD0 (io), 44 VCC (power)

## P87C51X2BBD
designator U?
80C51 8-Bit Microcontroller Family: 128 B RAM, 4 kB OTP, 2.7 to 5.5 V, Low Power, High Speed
footprint SOT389-1_N (Thin QFP, 44-Leads, Body 10x10mm, Pitch 0.8mm, IPC Medium Density)
footprint SOT389-1_L (Thin QFP, 44-Leads, Body 10x10mm, Pitch 0.8mm, IPC High Density)
footprint SOT389-1_M (Thin QFP, 44-Leads, Body 10x10mm, Pitch 0.8mm, IPC Low Density)
pins: 1 P1.5 (io), 2 P1.6 (io), 3 P1.7 (io), 4 RST (in), 5 P3.0/RxD (io), 6 NIC, 7 P3.1/TxD (io), 8 P3.2/~{INT}0 (io), 9 P3.3/~{INT}1 (io), 10 P3.4/T0 (io), 11 P3.5/T1 (io), 12 P3.6/~{WR} (io), 13 P3.7/~{RD} (io), 14 XTAL2 (out), 15 XTAL1 (in), 16 VSS (power), 17 NIC, 18 P2.0/A8 (io), 19 P2.1/A9 (io), 20 P2.2/A10 (io), 21 P2.3/A11 (io), 22 P2.4/A12 (io), 23 P2.5/A13 (io), 24 P2.6/A14 (io), 25 P2.7/A15 (io), 26 ~{PSEN} (out), 27 ALE (out), 28 NIC, 29 ~{EA}/VPP (in), 30 P0.7/AD7 (io), 31 P0.6/AD6 (io), 32 P0.5/AD5 (io), 33 P0.4/AD4 (io), 34 P0.3/AD3 (io), 35 P0.2/AD2 (io), 36 P0.1/AD1 (io), 37 P0.0/AD0 (io), 38 VCC (power), 39 NIC, 40 P1.0/T2 (io), 41 P1.1/T2EX (io), 42 P1.2 (io), 43 P1.3 (io), 44 P1.4 (io)

## P87C51X2BN
designator U?
80C51 8-Bit Microcontroller Family: 128 B RAM, 4 kB OTP, 2.7 to 5.5 V, Low Power, High Speed
footprint SOT129-1 (DIP, Plastic; 40 Leads; Row Spacing 15.24 mm; Pitch 2.54 mm)
pins: 1 P1.0/T2 (io), 2 P1.1/T2EX (io), 3 P1.2 (io), 4 P1.3 (io), 5 P1.4 (io), 6 P1.5 (io), 7 P1.6 (io), 8 P1.7 (io), 9 RST (in), 10 P3.0/RxD (io), 11 P3.1/TxD (io), 12 P3.2/~{INT}0 (io), 13 P3.3/~{INT}1 (io), 14 P3.4/T0 (io), 15 P3.5/T1 (io), 16 P3.6/~{WR} (io), 17 P3.7/~{RD} (io), 18 XTAL2 (out), 19 XTAL1 (in), 20 VSS (power), 21 P2.0/A8 (io), 22 P2.1/A9 (io), 23 P2.2/A10 (io), 24 P2.3/A11 (io), 25 P2.4/A12 (io), 26 P2.5/A13 (io), 27 P2.6/A14 (io), 28 P2.7/A15 (io), 29 ~{PSEN} (out), 30 ALE (out), 31 ~{EA}/VPP (in), 32 P0.7/AD7 (io), 33 P0.6/AD6 (io), 34 P0.5/AD5 (io), 35 P0.4/AD4 (io), 36 P0.3/AD3 (io), 37 P0.2/AD2 (io), 38 P0.1/AD1 (io), 39 P0.0/AD0 (io), 40 VCC (power)

## P87C51X2FA
designator U?
80C51 8-Bit Microcontroller Family: 128 B RAM, 4 kB OTP, 2.7 to 5.5 V, Low Power, High Speed
footprint SOT187-2_N (Leaded Chip Carrier, 44-Leads, Body 16.6x16.6mm, Pitch 1.27mm, IPC Medium Density)
footprint SOT187-2_L (Leaded Chip Carrier, 44-Leads, Body 16.6x16.6mm, Pitch 1.27mm, IPC High Density)
footprint SOT187-2_M (Leaded Chip Carrier, 44-Leads, Body 16.6x16.6mm, Pitch 1.27mm, IPC Low Density)
pins: 1 NIC, 2 P1.0/T2 (io), 3 P1.1/T2EX (io), 4 P1.2 (io), 5 P1.3 (io), 6 P1.4 (io), 7 P1.5 (io), 8 P1.6 (io), 9 P1.7 (io), 10 RST (in), 11 P3.0/RxD (io), 12 NIC, 13 P3.1/TxD (io), 14 P3.2/~{INT}0 (io), 15 P3.3/~{INT}1 (io), 16 P3.4/T0 (io), 17 P3.5/T1 (io), 18 P3.6/~{WR} (io), 19 P3.7/~{RD} (io), 20 XTAL2 (out), 21 XTAL1 (in), 22 VSS (power), 23 NIC, 24 P2.0/A8 (io), 25 P2.1/A9 (io), 26 P2.2/A10 (io), 27 P2.3/A11 (io), 28 P2.4/A12 (io), 29 P2.5/A13 (io), 30 P2.6/A14 (io), 31 P2.7/A15 (io), 32 ~{PSEN} (out), 33 ALE (out), 34 NIC, 35 ~{EA}/VPP (in), 36 P0.7/AD7 (io), 37 P0.6/AD6 (io), 38 P0.5/AD5 (io), 39 P0.4/AD4 (io), 40 P0.3/AD3 (io), 41 P0.2/AD2 (io), 42 P0.1/AD1 (io), 43 P0.0/AD0 (io), 44 VCC (power)

## P87C51X2FBD
designator U?
80C51 8-Bit Microcontroller Family: 128 B RAM, 4 kB OTP, 2.7 to 5.5 V, Low Power, High Speed
footprint SOT389-1_N (Thin QFP, 44-Leads, Body 10x10mm, Pitch 0.8mm, IPC Medium Density)
footprint SOT389-1_L (Thin QFP, 44-Leads, Body 10x10mm, Pitch 0.8mm, IPC High Density)
footprint SOT389-1_M (Thin QFP, 44-Leads, Body 10x10mm, Pitch 0.8mm, IPC Low Density)
pins: 1 P1.5 (io), 2 P1.6 (io), 3 P1.7 (io), 4 RST (in), 5 P3.0/RxD (io), 6 NIC, 7 P3.1/TxD (io), 8 P3.2/~{INT}0 (io), 9 P3.3/~{INT}1 (io), 10 P3.4/T0 (io), 11 P3.5/T1 (io), 12 P3.6/~{WR} (io), 13 P3.7/~{RD} (io), 14 XTAL2 (out), 15 XTAL1 (in), 16 VSS (power), 17 NIC, 18 P2.0/A8 (io), 19 P2.1/A9 (io), 20 P2.2/A10 (io), 21 P2.3/A11 (io), 22 P2.4/A12 (io), 23 P2.5/A13 (io), 24 P2.6/A14 (io), 25 P2.7/A15 (io), 26 ~{PSEN} (out), 27 ALE (out), 28 NIC, 29 ~{EA}/VPP (in), 30 P0.7/AD7 (io), 31 P0.6/AD6 (io), 32 P0.5/AD5 (io), 33 P0.4/AD4 (io), 34 P0.3/AD3 (io), 35 P0.2/AD2 (io), 36 P0.1/AD1 (io), 37 P0.0/AD0 (io), 38 VCC (power), 39 NIC, 40 P1.0/T2 (io), 41 P1.1/T2EX (io), 42 P1.2 (io), 43 P1.3 (io), 44 P1.4 (io)

## P87C52SBAA
designator U?
80C51 8-Bit Microcontroller Family: 256 B RAM, 8 kB OTP, 2.7V-5.5V, Low Power, High Speed
footprint SOT187-2_N (Leaded Chip Carrier, 44-Leads, Body 16.6x16.6mm, Pitch 1.27mm, IPC Medium Density)
footprint SOT187-2_L (Leaded Chip Carrier, 44-Leads, Body 16.6x16.6mm, Pitch 1.27mm, IPC High Density)
footprint SOT187-2_M (Leaded Chip Carrier, 44-Leads, Body 16.6x16.6mm, Pitch 1.27mm, IPC Low Density)
pins: 1 NIC, 2 P1.0/T2 (io), 3 P1.1/T2EX (io), 4 P1.2 (io), 5 P1.3 (io), 6 P1.4 (io), 7 P1.5 (io), 8 P1.6 (io), 9 P1.7 (io), 10 RST (in), 11 P3.0/RxD (io), 12 NIC, 13 P3.1/TxD (io), 14 P3.2/~{INT}0 (io), 15 P3.3/~{INT}1 (io), 16 P3.4/T0 (io), 17 P3.5/T1 (io), 18 P3.6/~{WR} (io), 19 P3.7/~{RD} (io), 20 XTAL2 (out), 21 XTAL1 (in), 22 VSS (power), 23 NIC, 24 P2.0/A8 (io), 25 P2.1/A9 (io), 26 P2.2/A10 (io), 27 P2.3/A11 (io), 28 P2.4/A12 (io), 29 P2.5/A13 (io), 30 P2.6/A14 (io), 31 P2.7/A15 (io), 32 ~{PSEN} (out), 33 ALE (out), 34 NIC, 35 ~{EA}/VPP (in), 36 P0.7/AD7 (io), 37 P0.6/AD6 (io), 38 P0.5/AD5 (io), 39 P0.4/AD4 (io), 40 P0.3/AD3 (io), 41 P0.2/AD2 (io), 42 P0.1/AD1 (io), 43 P0.0/AD0 (io), 44 VCC (power)

## P87C52SBBB
designator U?
80C51 8-Bit Microcontroller Family: 256 B RAM, 8 kB OTP, 2.7V-5.5V, Low Power, High Speed
footprint SOT307-2_N (QFP, 44-Leads, Body 10x10mm, Pitch 0.8mm, IPC Medium Density)
footprint SOT307-2_L (QFP, 44-Leads, Body 10x10mm, Pitch 0.8mm, IPC High Density)
footprint SOT307-2_M (QFP, 44-Leads, Body 10x10mm, Pitch 0.8mm, IPC Low Density)
pins: 1 P1.5 (io), 2 P1.6 (io), 3 P1.7 (io), 4 RST (in), 5 P3.0/RxD (io), 6 NIC, 7 P3.1/TxD (io), 8 P3.2/~{INT}0 (io), 9 P3.3/~{INT}1 (io), 10 P3.4/T0 (io), 11 P3.5/T1 (io), 12 P3.6/~{WR} (io), 13 P3.7/~{RD} (io), 14 XTAL2 (out), 15 XTAL1 (in), 16 VSS (power), 17 NIC, 18 P2.0/A8 (io), 19 P2.1/A9 (io), 20 P2.2/A10 (io), 21 P2.3/A11 (io), 22 P2.4/A12 (io), 23 P2.5/A13 (io), 24 P2.6/A14 (io), 25 P2.7/A15 (io), 26 ~{PSEN} (out), 27 ALE (out), 28 NIC, 29 ~{EA}/VPP (in), 30 P0.7/AD7 (io), 31 P0.6/AD6 (io), 32 P0.5/AD5 (io), 33 P0.4/AD4 (io), 34 P0.3/AD3 (io), 35 P0.2/AD2 (io), 36 P0.1/AD1 (io), 37 P0.0/AD0 (io), 38 VCC (power), 39 NIC, 40 P1.0/T2 (io), 41 P1.1/T2EX (io), 42 P1.2 (io), 43 P1.3 (io), 44 P1.4 (io)

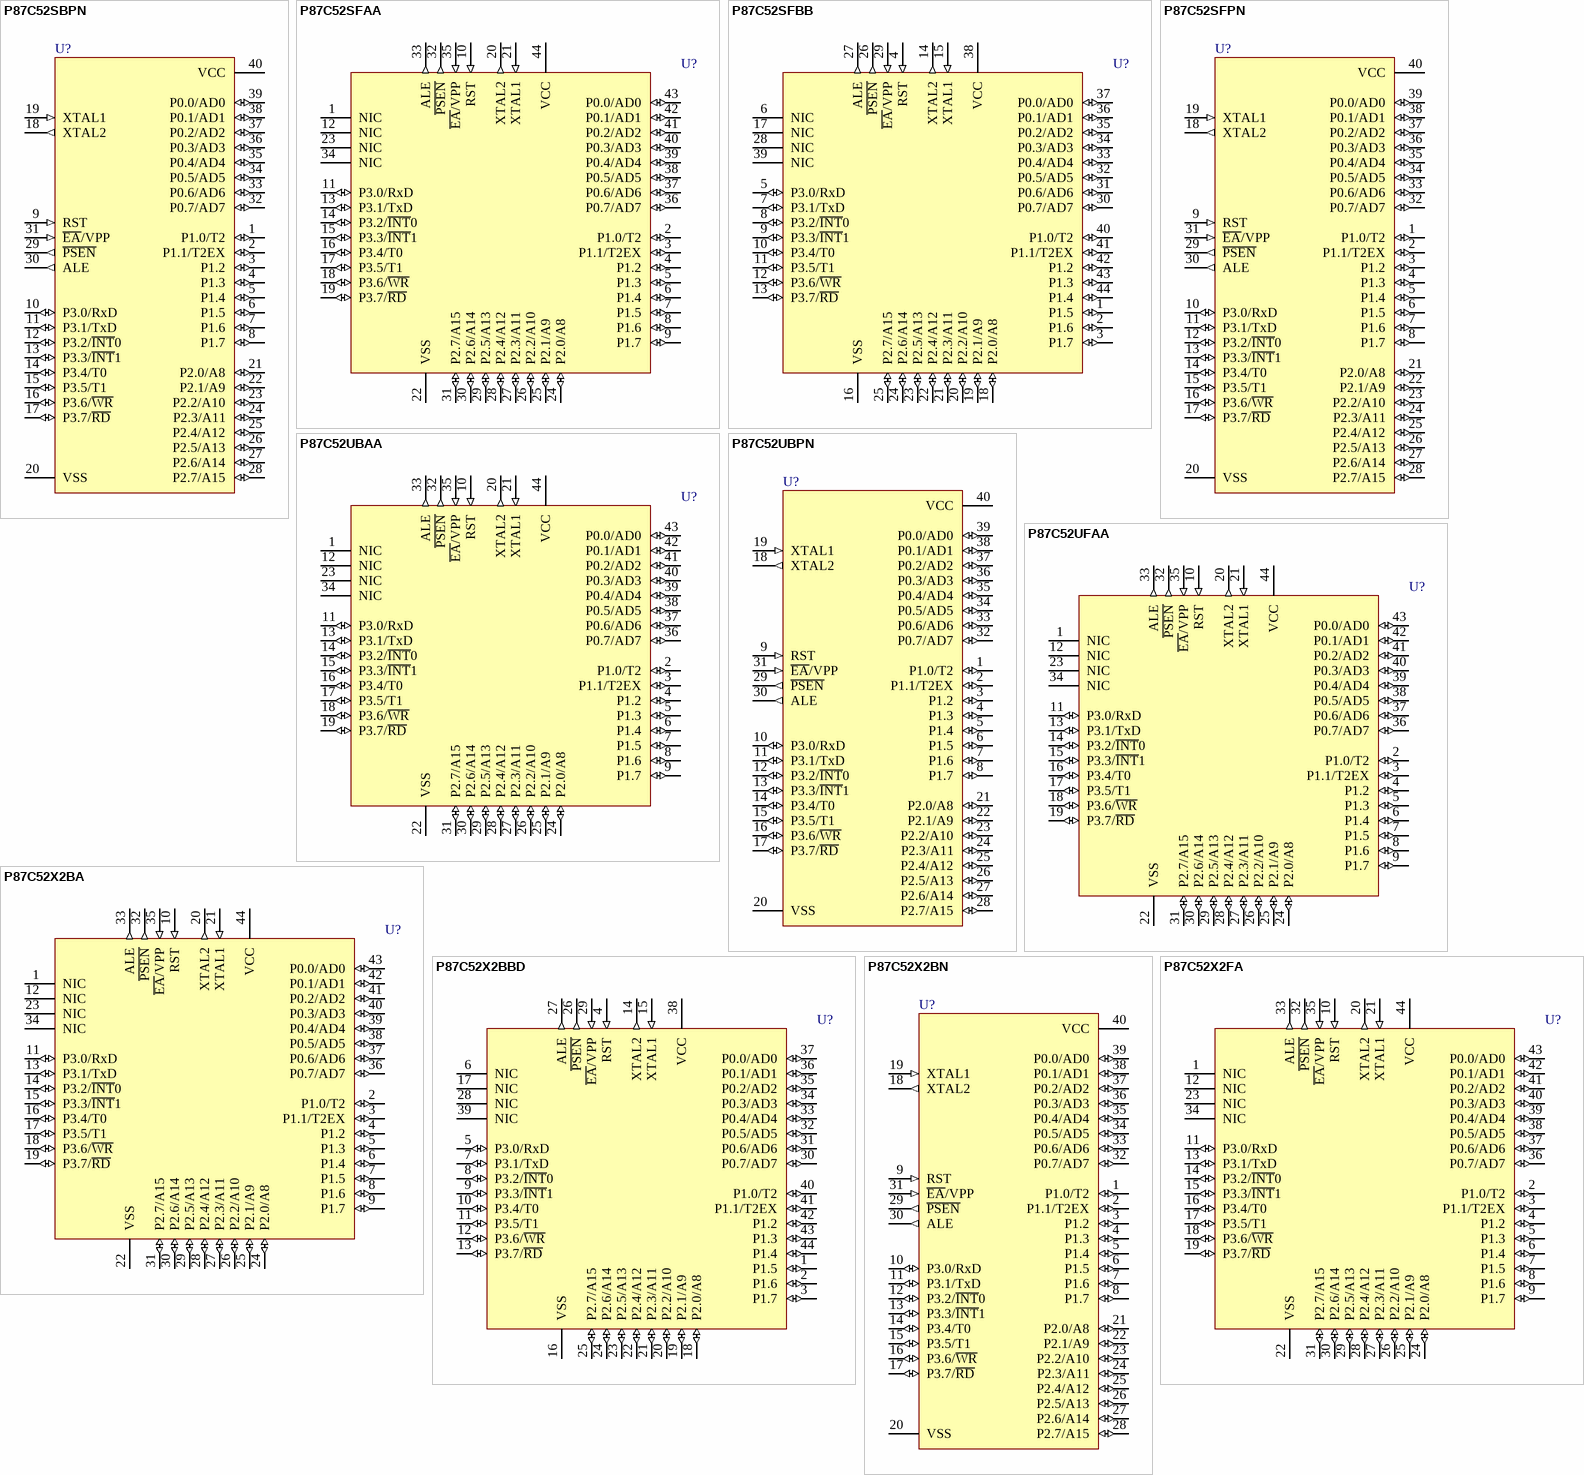
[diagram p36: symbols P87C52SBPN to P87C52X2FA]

## P87C52SBPN
designator U?
80C51 8-Bit Microcontroller Family: 256 B RAM, 8 kB OTP, 2.7V-5.5V, Low Power, High Speed
footprint SOT129-1 (DIP, Plastic; 40 Leads; Row Spacing 15.24 mm; Pitch 2.54 mm)
pins: 1 P1.0/T2 (io), 2 P1.1/T2EX (io), 3 P1.2 (io), 4 P1.3 (io), 5 P1.4 (io), 6 P1.5 (io), 7 P1.6 (io), 8 P1.7 (io), 9 RST (in), 10 P3.0/RxD (io), 11 P3.1/TxD (io), 12 P3.2/~{INT}0 (io), 13 P3.3/~{INT}1 (io), 14 P3.4/T0 (io), 15 P3.5/T1 (io), 16 P3.6/~{WR} (io), 17 P3.7/~{RD} (io), 18 XTAL2 (out), 19 XTAL1 (in), 20 VSS (power), 21 P2.0/A8 (io), 22 P2.1/A9 (io), 23 P2.2/A10 (io), 24 P2.3/A11 (io), 25 P2.4/A12 (io), 26 P2.5/A13 (io), 27 P2.6/A14 (io), 28 P2.7/A15 (io), 29 ~{PSEN} (out), 30 ALE (out), 31 ~{EA}/VPP (in), 32 P0.7/AD7 (io), 33 P0.6/AD6 (io), 34 P0.5/AD5 (io), 35 P0.4/AD4 (io), 36 P0.3/AD3 (io), 37 P0.2/AD2 (io), 38 P0.1/AD1 (io), 39 P0.0/AD0 (io), 40 VCC (power)

## P87C52SFAA
designator U?
80C51 8-Bit Microcontroller Family: 256 B RAM, 8 kB OTP, 2.7V-5.5V, Low Power, High Speed
footprint SOT187-2_N (Leaded Chip Carrier, 44-Leads, Body 16.6x16.6mm, Pitch 1.27mm, IPC Medium Density)
footprint SOT187-2_L (Leaded Chip Carrier, 44-Leads, Body 16.6x16.6mm, Pitch 1.27mm, IPC High Density)
footprint SOT187-2_M (Leaded Chip Carrier, 44-Leads, Body 16.6x16.6mm, Pitch 1.27mm, IPC Low Density)
pins: 1 NIC, 2 P1.0/T2 (io), 3 P1.1/T2EX (io), 4 P1.2 (io), 5 P1.3 (io), 6 P1.4 (io), 7 P1.5 (io), 8 P1.6 (io), 9 P1.7 (io), 10 RST (in), 11 P3.0/RxD (io), 12 NIC, 13 P3.1/TxD (io), 14 P3.2/~{INT}0 (io), 15 P3.3/~{INT}1 (io), 16 P3.4/T0 (io), 17 P3.5/T1 (io), 18 P3.6/~{WR} (io), 19 P3.7/~{RD} (io), 20 XTAL2 (out), 21 XTAL1 (in), 22 VSS (power), 23 NIC, 24 P2.0/A8 (io), 25 P2.1/A9 (io), 26 P2.2/A10 (io), 27 P2.3/A11 (io), 28 P2.4/A12 (io), 29 P2.5/A13 (io), 30 P2.6/A14 (io), 31 P2.7/A15 (io), 32 ~{PSEN} (out), 33 ALE (out), 34 NIC, 35 ~{EA}/VPP (in), 36 P0.7/AD7 (io), 37 P0.6/AD6 (io), 38 P0.5/AD5 (io), 39 P0.4/AD4 (io), 40 P0.3/AD3 (io), 41 P0.2/AD2 (io), 42 P0.1/AD1 (io), 43 P0.0/AD0 (io), 44 VCC (power)

## P87C52SFBB
designator U?
80C51 8-Bit Microcontroller Family: 256 B RAM, 8 kB OTP, 2.7V-5.5V, Low Power, High Speed
footprint SOT307-2_N (QFP, 44-Leads, Body 10x10mm, Pitch 0.8mm, IPC Medium Density)
footprint SOT307-2_L (QFP, 44-Leads, Body 10x10mm, Pitch 0.8mm, IPC High Density)
footprint SOT307-2_M (QFP, 44-Leads, Body 10x10mm, Pitch 0.8mm, IPC Low Density)
pins: 1 P1.5 (io), 2 P1.6 (io), 3 P1.7 (io), 4 RST (in), 5 P3.0/RxD (io), 6 NIC, 7 P3.1/TxD (io), 8 P3.2/~{INT}0 (io), 9 P3.3/~{INT}1 (io), 10 P3.4/T0 (io), 11 P3.5/T1 (io), 12 P3.6/~{WR} (io), 13 P3.7/~{RD} (io), 14 XTAL2 (out), 15 XTAL1 (in), 16 VSS (power), 17 NIC, 18 P2.0/A8 (io), 19 P2.1/A9 (io), 20 P2.2/A10 (io), 21 P2.3/A11 (io), 22 P2.4/A12 (io), 23 P2.5/A13 (io), 24 P2.6/A14 (io), 25 P2.7/A15 (io), 26 ~{PSEN} (out), 27 ALE (out), 28 NIC, 29 ~{EA}/VPP (in), 30 P0.7/AD7 (io), 31 P0.6/AD6 (io), 32 P0.5/AD5 (io), 33 P0.4/AD4 (io), 34 P0.3/AD3 (io), 35 P0.2/AD2 (io), 36 P0.1/AD1 (io), 37 P0.0/AD0 (io), 38 VCC (power), 39 NIC, 40 P1.0/T2 (io), 41 P1.1/T2EX (io), 42 P1.2 (io), 43 P1.3 (io), 44 P1.4 (io)

## P87C52SFPN
designator U?
80C51 8-Bit Microcontroller Family: 256 B RAM, 8 kB OTP, 2.7V-5.5V, Low Power, High Speed
footprint SOT129-1 (DIP, Plastic; 40 Leads; Row Spacing 15.24 mm; Pitch 2.54 mm)
pins: 1 P1.0/T2 (io), 2 P1.1/T2EX (io), 3 P1.2 (io), 4 P1.3 (io), 5 P1.4 (io), 6 P1.5 (io), 7 P1.6 (io), 8 P1.7 (io), 9 RST (in), 10 P3.0/RxD (io), 11 P3.1/TxD (io), 12 P3.2/~{INT}0 (io), 13 P3.3/~{INT}1 (io), 14 P3.4/T0 (io), 15 P3.5/T1 (io), 16 P3.6/~{WR} (io), 17 P3.7/~{RD} (io), 18 XTAL2 (out), 19 XTAL1 (in), 20 VSS (power), 21 P2.0/A8 (io), 22 P2.1/A9 (io), 23 P2.2/A10 (io), 24 P2.3/A11 (io), 25 P2.4/A12 (io), 26 P2.5/A13 (io), 27 P2.6/A14 (io), 28 P2.7/A15 (io), 29 ~{PSEN} (out), 30 ALE (out), 31 ~{EA}/VPP (in), 32 P0.7/AD7 (io), 33 P0.6/AD6 (io), 34 P0.5/AD5 (io), 35 P0.4/AD4 (io), 36 P0.3/AD3 (io), 37 P0.2/AD2 (io), 38 P0.1/AD1 (io), 39 P0.0/AD0 (io), 40 VCC (power)

## P87C52UBAA
designator U?
80C51 8-Bit Microcontroller Family: 256 B RAM, 8 kB OTP, 5V, Low Power, High Speed
footprint SOT187-2_N (Leaded Chip Carrier, 44-Leads, Body 16.6x16.6mm, Pitch 1.27mm, IPC Medium Density)
footprint SOT187-2_L (Leaded Chip Carrier, 44-Leads, Body 16.6x16.6mm, Pitch 1.27mm, IPC High Density)
footprint SOT187-2_M (Leaded Chip Carrier, 44-Leads, Body 16.6x16.6mm, Pitch 1.27mm, IPC Low Density)
pins: 1 NIC, 2 P1.0/T2 (io), 3 P1.1/T2EX (io), 4 P1.2 (io), 5 P1.3 (io), 6 P1.4 (io), 7 P1.5 (io), 8 P1.6 (io), 9 P1.7 (io), 10 RST (in), 11 P3.0/RxD (io), 12 NIC, 13 P3.1/TxD (io), 14 P3.2/~{INT}0 (io), 15 P3.3/~{INT}1 (io), 16 P3.4/T0 (io), 17 P3.5/T1 (io), 18 P3.6/~{WR} (io), 19 P3.7/~{RD} (io), 20 XTAL2 (out), 21 XTAL1 (in), 22 VSS (power), 23 NIC, 24 P2.0/A8 (io), 25 P2.1/A9 (io), 26 P2.2/A10 (io), 27 P2.3/A11 (io), 28 P2.4/A12 (io), 29 P2.5/A13 (io), 30 P2.6/A14 (io), 31 P2.7/A15 (io), 32 ~{PSEN} (out), 33 ALE (out), 34 NIC, 35 ~{EA}/VPP (in), 36 P0.7/AD7 (io), 37 P0.6/AD6 (io), 38 P0.5/AD5 (io), 39 P0.4/AD4 (io), 40 P0.3/AD3 (io), 41 P0.2/AD2 (io), 42 P0.1/AD1 (io), 43 P0.0/AD0 (io), 44 VCC (power)

## P87C52UBPN
designator U?
80C51 8-Bit Microcontroller Family: 256 B RAM, 8 kB OTP, 5V, Low Power, High Speed
footprint SOT129-1 (DIP, Plastic; 40 Leads; Row Spacing 15.24 mm; Pitch 2.54 mm)
pins: 1 P1.0/T2 (io), 2 P1.1/T2EX (io), 3 P1.2 (io), 4 P1.3 (io), 5 P1.4 (io), 6 P1.5 (io), 7 P1.6 (io), 8 P1.7 (io), 9 RST (in), 10 P3.0/RxD (io), 11 P3.1/TxD (io), 12 P3.2/~{INT}0 (io), 13 P3.3/~{INT}1 (io), 14 P3.4/T0 (io), 15 P3.5/T1 (io), 16 P3.6/~{WR} (io), 17 P3.7/~{RD} (io), 18 XTAL2 (out), 19 XTAL1 (in), 20 VSS (power), 21 P2.0/A8 (io), 22 P2.1/A9 (io), 23 P2.2/A10 (io), 24 P2.3/A11 (io), 25 P2.4/A12 (io), 26 P2.5/A13 (io), 27 P2.6/A14 (io), 28 P2.7/A15 (io), 29 ~{PSEN} (out), 30 ALE (out), 31 ~{EA}/VPP (in), 32 P0.7/AD7 (io), 33 P0.6/AD6 (io), 34 P0.5/AD5 (io), 35 P0.4/AD4 (io), 36 P0.3/AD3 (io), 37 P0.2/AD2 (io), 38 P0.1/AD1 (io), 39 P0.0/AD0 (io), 40 VCC (power)

## P87C52UFAA
designator U?
80C51 8-Bit Microcontroller Family: 256 B RAM, 8 kB OTP, 5V, Low Power, High Speed
footprint SOT187-2_N (Leaded Chip Carrier, 44-Leads, Body 16.6x16.6mm, Pitch 1.27mm, IPC Medium Density)
footprint SOT187-2_L (Leaded Chip Carrier, 44-Leads, Body 16.6x16.6mm, Pitch 1.27mm, IPC High Density)
footprint SOT187-2_M (Leaded Chip Carrier, 44-Leads, Body 16.6x16.6mm, Pitch 1.27mm, IPC Low Density)
pins: 1 NIC, 2 P1.0/T2 (io), 3 P1.1/T2EX (io), 4 P1.2 (io), 5 P1.3 (io), 6 P1.4 (io), 7 P1.5 (io), 8 P1.6 (io), 9 P1.7 (io), 10 RST (in), 11 P3.0/RxD (io), 12 NIC, 13 P3.1/TxD (io), 14 P3.2/~{INT}0 (io), 15 P3.3/~{INT}1 (io), 16 P3.4/T0 (io), 17 P3.5/T1 (io), 18 P3.6/~{WR} (io), 19 P3.7/~{RD} (io), 20 XTAL2 (out), 21 XTAL1 (in), 22 VSS (power), 23 NIC, 24 P2.0/A8 (io), 25 P2.1/A9 (io), 26 P2.2/A10 (io), 27 P2.3/A11 (io), 28 P2.4/A12 (io), 29 P2.5/A13 (io), 30 P2.6/A14 (io), 31 P2.7/A15 (io), 32 ~{PSEN} (out), 33 ALE (out), 34 NIC, 35 ~{EA}/VPP (in), 36 P0.7/AD7 (io), 37 P0.6/AD6 (io), 38 P0.5/AD5 (io), 39 P0.4/AD4 (io), 40 P0.3/AD3 (io), 41 P0.2/AD2 (io), 42 P0.1/AD1 (io), 43 P0.0/AD0 (io), 44 VCC (power)

## P87C52X2BA
designator U?
80C51 8-Bit Microcontroller Family: 256 B RAM, 8 kB OTP, 2.7 to 5.5 V, Low Power, High Speed
footprint SOT187-2_N (Leaded Chip Carrier, 44-Leads, Body 16.6x16.6mm, Pitch 1.27mm, IPC Medium Density)
footprint SOT187-2_L (Leaded Chip Carrier, 44-Leads, Body 16.6x16.6mm, Pitch 1.27mm, IPC High Density)
footprint SOT187-2_M (Leaded Chip Carrier, 44-Leads, Body 16.6x16.6mm, Pitch 1.27mm, IPC Low Density)
pins: 1 NIC, 2 P1.0/T2 (io), 3 P1.1/T2EX (io), 4 P1.2 (io), 5 P1.3 (io), 6 P1.4 (io), 7 P1.5 (io), 8 P1.6 (io), 9 P1.7 (io), 10 RST (in), 11 P3.0/RxD (io), 12 NIC, 13 P3.1/TxD (io), 14 P3.2/~{INT}0 (io), 15 P3.3/~{INT}1 (io), 16 P3.4/T0 (io), 17 P3.5/T1 (io), 18 P3.6/~{WR} (io), 19 P3.7/~{RD} (io), 20 XTAL2 (out), 21 XTAL1 (in), 22 VSS (power), 23 NIC, 24 P2.0/A8 (io), 25 P2.1/A9 (io), 26 P2.2/A10 (io), 27 P2.3/A11 (io), 28 P2.4/A12 (io), 29 P2.5/A13 (io), 30 P2.6/A14 (io), 31 P2.7/A15 (io), 32 ~{PSEN} (out), 33 ALE (out), 34 NIC, 35 ~{EA}/VPP (in), 36 P0.7/AD7 (io), 37 P0.6/AD6 (io), 38 P0.5/AD5 (io), 39 P0.4/AD4 (io), 40 P0.3/AD3 (io), 41 P0.2/AD2 (io), 42 P0.1/AD1 (io), 43 P0.0/AD0 (io), 44 VCC (power)

## P87C52X2BBD
designator U?
80C51 8-Bit Microcontroller Family: 256 B RAM, 8 kB OTP, 2.7 to 5.5 V, Low Power, High Speed
footprint SOT389-1_N (Thin QFP, 44-Leads, Body 10x10mm, Pitch 0.8mm, IPC Medium Density)
footprint SOT389-1_L (Thin QFP, 44-Leads, Body 10x10mm, Pitch 0.8mm, IPC High Density)
footprint SOT389-1_M (Thin QFP, 44-Leads, Body 10x10mm, Pitch 0.8mm, IPC Low Density)
pins: 1 P1.5 (io), 2 P1.6 (io), 3 P1.7 (io), 4 RST (in), 5 P3.0/RxD (io), 6 NIC, 7 P3.1/TxD (io), 8 P3.2/~{INT}0 (io), 9 P3.3/~{INT}1 (io), 10 P3.4/T0 (io), 11 P3.5/T1 (io), 12 P3.6/~{WR} (io), 13 P3.7/~{RD} (io), 14 XTAL2 (out), 15 XTAL1 (in), 16 VSS (power), 17 NIC, 18 P2.0/A8 (io), 19 P2.1/A9 (io), 20 P2.2/A10 (io), 21 P2.3/A11 (io), 22 P2.4/A12 (io), 23 P2.5/A13 (io), 24 P2.6/A14 (io), 25 P2.7/A15 (io), 26 ~{PSEN} (out), 27 ALE (out), 28 NIC, 29 ~{EA}/VPP (in), 30 P0.7/AD7 (io), 31 P0.6/AD6 (io), 32 P0.5/AD5 (io), 33 P0.4/AD4 (io), 34 P0.3/AD3 (io), 35 P0.2/AD2 (io), 36 P0.1/AD1 (io), 37 P0.0/AD0 (io), 38 VCC (power), 39 NIC, 40 P1.0/T2 (io), 41 P1.1/T2EX (io), 42 P1.2 (io), 43 P1.3 (io), 44 P1.4 (io)

## P87C52X2BN
designator U?
80C51 8-Bit Microcontroller Family: 256 B RAM, 8 kB OTP, 2.7 to 5.5 V, Low Power, High Speed
footprint SOT129-1 (DIP, Plastic; 40 Leads; Row Spacing 15.24 mm; Pitch 2.54 mm)
pins: 1 P1.0/T2 (io), 2 P1.1/T2EX (io), 3 P1.2 (io), 4 P1.3 (io), 5 P1.4 (io), 6 P1.5 (io), 7 P1.6 (io), 8 P1.7 (io), 9 RST (in), 10 P3.0/RxD (io), 11 P3.1/TxD (io), 12 P3.2/~{INT}0 (io), 13 P3.3/~{INT}1 (io), 14 P3.4/T0 (io), 15 P3.5/T1 (io), 16 P3.6/~{WR} (io), 17 P3.7/~{RD} (io), 18 XTAL2 (out), 19 XTAL1 (in), 20 VSS (power), 21 P2.0/A8 (io), 22 P2.1/A9 (io), 23 P2.2/A10 (io), 24 P2.3/A11 (io), 25 P2.4/A12 (io), 26 P2.5/A13 (io), 27 P2.6/A14 (io), 28 P2.7/A15 (io), 29 ~{PSEN} (out), 30 ALE (out), 31 ~{EA}/VPP (in), 32 P0.7/AD7 (io), 33 P0.6/AD6 (io), 34 P0.5/AD5 (io), 35 P0.4/AD4 (io), 36 P0.3/AD3 (io), 37 P0.2/AD2 (io), 38 P0.1/AD1 (io), 39 P0.0/AD0 (io), 40 VCC (power)

## P87C52X2FA
designator U?
80C51 8-Bit Microcontroller Family: 256 B RAM, 8 kB OTP, 2.7 to 5.5 V, Low Power, High Speed
footprint SOT187-2_N (Leaded Chip Carrier, 44-Leads, Body 16.6x16.6mm, Pitch 1.27mm, IPC Medium Density)
footprint SOT187-2_L (Leaded Chip Carrier, 44-Leads, Body 16.6x16.6mm, Pitch 1.27mm, IPC High Density)
footprint SOT187-2_M (Leaded Chip Carrier, 44-Leads, Body 16.6x16.6mm, Pitch 1.27mm, IPC Low Density)
pins: 1 NIC, 2 P1.0/T2 (io), 3 P1.1/T2EX (io), 4 P1.2 (io), 5 P1.3 (io), 6 P1.4 (io), 7 P1.5 (io), 8 P1.6 (io), 9 P1.7 (io), 10 RST (in), 11 P3.0/RxD (io), 12 NIC, 13 P3.1/TxD (io), 14 P3.2/~{INT}0 (io), 15 P3.3/~{INT}1 (io), 16 P3.4/T0 (io), 17 P3.5/T1 (io), 18 P3.6/~{WR} (io), 19 P3.7/~{RD} (io), 20 XTAL2 (out), 21 XTAL1 (in), 22 VSS (power), 23 NIC, 24 P2.0/A8 (io), 25 P2.1/A9 (io), 26 P2.2/A10 (io), 27 P2.3/A11 (io), 28 P2.4/A12 (io), 29 P2.5/A13 (io), 30 P2.6/A14 (io), 31 P2.7/A15 (io), 32 ~{PSEN} (out), 33 ALE (out), 34 NIC, 35 ~{EA}/VPP (in), 36 P0.7/AD7 (io), 37 P0.6/AD6 (io), 38 P0.5/AD5 (io), 39 P0.4/AD4 (io), 40 P0.3/AD3 (io), 41 P0.2/AD2 (io), 42 P0.1/AD1 (io), 43 P0.0/AD0 (io), 44 VCC (power)

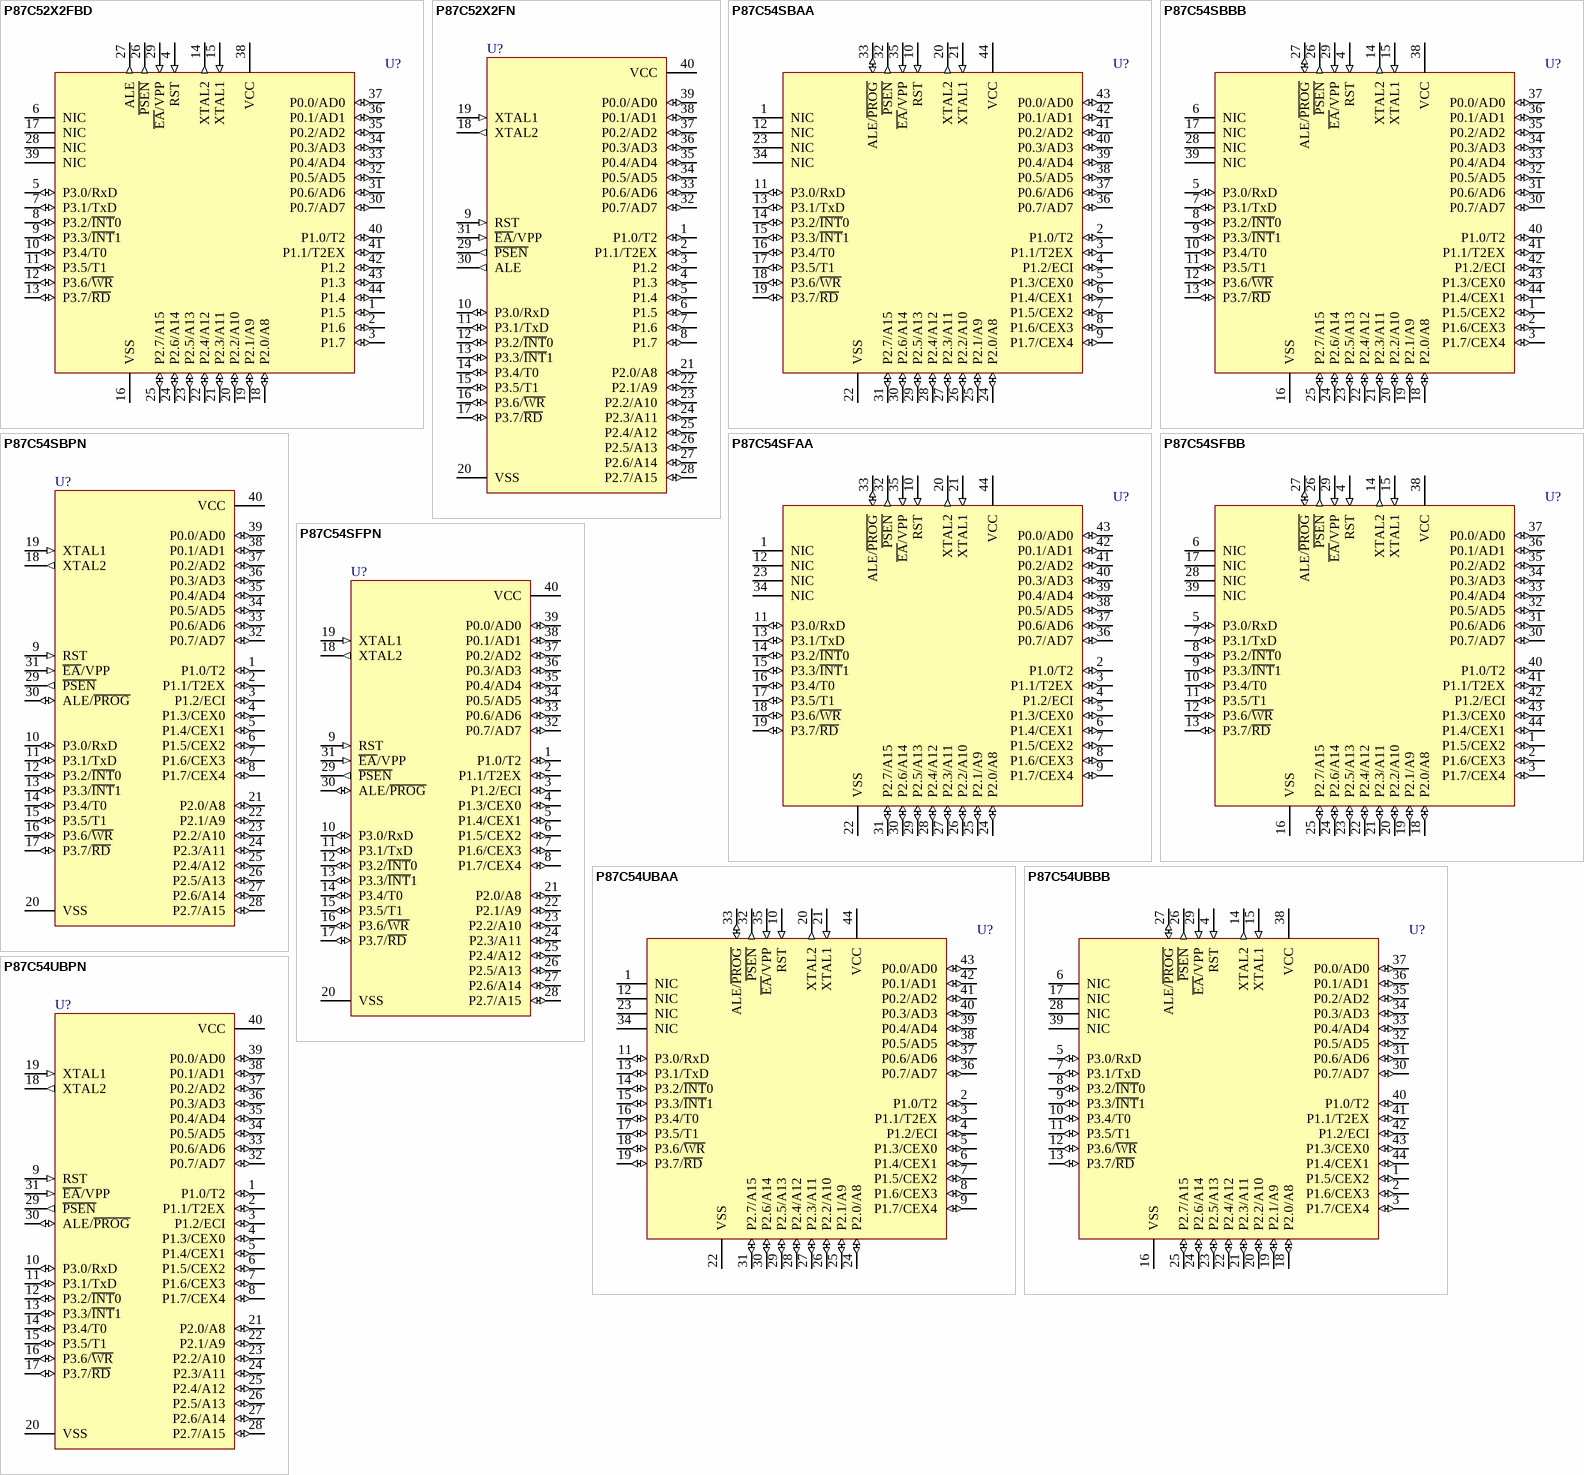
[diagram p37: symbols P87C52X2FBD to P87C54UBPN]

## P87C52X2FBD
designator U?
80C51 8-Bit Microcontroller Family: 256 B RAM, 8 kB OTP, 2.7 to 5.5 V, Low Power, High Speed
footprint SOT389-1_N (Thin QFP, 44-Leads, Body 10x10mm, Pitch 0.8mm, IPC Medium Density)
footprint SOT389-1_L (Thin QFP, 44-Leads, Body 10x10mm, Pitch 0.8mm, IPC High Density)
footprint SOT389-1_M (Thin QFP, 44-Leads, Body 10x10mm, Pitch 0.8mm, IPC Low Density)
pins: 1 P1.5 (io), 2 P1.6 (io), 3 P1.7 (io), 4 RST (in), 5 P3.0/RxD (io), 6 NIC, 7 P3.1/TxD (io), 8 P3.2/~{INT}0 (io), 9 P3.3/~{INT}1 (io), 10 P3.4/T0 (io), 11 P3.5/T1 (io), 12 P3.6/~{WR} (io), 13 P3.7/~{RD} (io), 14 XTAL2 (out), 15 XTAL1 (in), 16 VSS (power), 17 NIC, 18 P2.0/A8 (io), 19 P2.1/A9 (io), 20 P2.2/A10 (io), 21 P2.3/A11 (io), 22 P2.4/A12 (io), 23 P2.5/A13 (io), 24 P2.6/A14 (io), 25 P2.7/A15 (io), 26 ~{PSEN} (out), 27 ALE (out), 28 NIC, 29 ~{EA}/VPP (in), 30 P0.7/AD7 (io), 31 P0.6/AD6 (io), 32 P0.5/AD5 (io), 33 P0.4/AD4 (io), 34 P0.3/AD3 (io), 35 P0.2/AD2 (io), 36 P0.1/AD1 (io), 37 P0.0/AD0 (io), 38 VCC (power), 39 NIC, 40 P1.0/T2 (io), 41 P1.1/T2EX (io), 42 P1.2 (io), 43 P1.3 (io), 44 P1.4 (io)

## P87C52X2FN
designator U?
80C51 8-Bit Microcontroller Family: 256 B RAM, 8 kB OTP, 2.7 to 5.5 V, Low Power, High Speed
footprint SOT129-1 (DIP, Plastic; 40 Leads; Row Spacing 15.24 mm; Pitch 2.54 mm)
pins: 1 P1.0/T2 (io), 2 P1.1/T2EX (io), 3 P1.2 (io), 4 P1.3 (io), 5 P1.4 (io), 6 P1.5 (io), 7 P1.6 (io), 8 P1.7 (io), 9 RST (in), 10 P3.0/RxD (io), 11 P3.1/TxD (io), 12 P3.2/~{INT}0 (io), 13 P3.3/~{INT}1 (io), 14 P3.4/T0 (io), 15 P3.5/T1 (io), 16 P3.6/~{WR} (io), 17 P3.7/~{RD} (io), 18 XTAL2 (out), 19 XTAL1 (in), 20 VSS (power), 21 P2.0/A8 (io), 22 P2.1/A9 (io), 23 P2.2/A10 (io), 24 P2.3/A11 (io), 25 P2.4/A12 (io), 26 P2.5/A13 (io), 27 P2.6/A14 (io), 28 P2.7/A15 (io), 29 ~{PSEN} (out), 30 ALE (out), 31 ~{EA}/VPP (in), 32 P0.7/AD7 (io), 33 P0.6/AD6 (io), 34 P0.5/AD5 (io), 35 P0.4/AD4 (io), 36 P0.3/AD3 (io), 37 P0.2/AD2 (io), 38 P0.1/AD1 (io), 39 P0.0/AD0 (io), 40 VCC (power)

## P87C54SBAA
designator U?
80C51 8-Bit Microcontroller Family: 256 B RAM, 16 kB OTP, 2.7V-5.5V, Low Power, High Speed
footprint SOT187-2_N (Leaded Chip Carrier, 44-Leads, Body 16.6x16.6mm, Pitch 1.27mm, IPC Medium Density)
footprint SOT187-2_L (Leaded Chip Carrier, 44-Leads, Body 16.6x16.6mm, Pitch 1.27mm, IPC High Density)
footprint SOT187-2_M (Leaded Chip Carrier, 44-Leads, Body 16.6x16.6mm, Pitch 1.27mm, IPC Low Density)
pins: 1 NIC, 2 P1.0/T2 (io), 3 P1.1/T2EX (io), 4 P1.2/ECI (io), 5 P1.3/CEX0 (io), 6 P1.4/CEX1 (io), 7 P1.5/CEX2 (io), 8 P1.6/CEX3 (io), 9 P1.7/CEX4 (io), 10 RST (in), 11 P3.0/RxD (io), 12 NIC, 13 P3.1/TxD (io), 14 P3.2/~{INT}0 (io), 15 P3.3/~{INT}1 (io), 16 P3.4/T0 (io), 17 P3.5/T1 (io), 18 P3.6/~{WR} (io), 19 P3.7/~{RD} (io), 20 XTAL2 (out), 21 XTAL1 (in), 22 VSS (power), 23 NIC, 24 P2.0/A8 (io), 25 P2.1/A9 (io), 26 P2.2/A10 (io), 27 P2.3/A11 (io), 28 P2.4/A12 (io), 29 P2.5/A13 (io), 30 P2.6/A14 (io), 31 P2.7/A15 (io), 32 ~{PSEN} (out), 33 ALE/~{PROG} (io), 34 NIC, 35 ~{EA}/VPP (in), 36 P0.7/AD7 (io), 37 P0.6/AD6 (io), 38 P0.5/AD5 (io), 39 P0.4/AD4 (io), 40 P0.3/AD3 (io), 41 P0.2/AD2 (io), 42 P0.1/AD1 (io), 43 P0.0/AD0 (io), 44 VCC (power)

## P87C54SBBB
designator U?
80C51 8-Bit Microcontroller Family: 256 B RAM, 16 kB OTP, 2.7V-5.5V, Low Power, High Speed
footprint SOT307-2_N (QFP, 44-Leads, Body 10x10mm, Pitch 0.8mm, IPC Medium Density)
footprint SOT307-2_L (QFP, 44-Leads, Body 10x10mm, Pitch 0.8mm, IPC High Density)
footprint SOT307-2_M (QFP, 44-Leads, Body 10x10mm, Pitch 0.8mm, IPC Low Density)
pins: 1 P1.5/CEX2 (io), 2 P1.6/CEX3 (io), 3 P1.7/CEX4 (io), 4 RST (in), 5 P3.0/RxD (io), 6 NIC, 7 P3.1/TxD (io), 8 P3.2/~{INT}0 (io), 9 P3.3/~{INT}1 (io), 10 P3.4/T0 (io), 11 P3.5/T1 (io), 12 P3.6/~{WR} (io), 13 P3.7/~{RD} (io), 14 XTAL2 (out), 15 XTAL1 (in), 16 VSS (power), 17 NIC, 18 P2.0/A8 (io), 19 P2.1/A9 (io), 20 P2.2/A10 (io), 21 P2.3/A11 (io), 22 P2.4/A12 (io), 23 P2.5/A13 (io), 24 P2.6/A14 (io), 25 P2.7/A15 (io), 26 ~{PSEN} (out), 27 ALE/~{PROG} (io), 28 NIC, 29 ~{EA}/VPP (in), 30 P0.7/AD7 (io), 31 P0.6/AD6 (io), 32 P0.5/AD5 (io), 33 P0.4/AD4 (io), 34 P0.3/AD3 (io), 35 P0.2/AD2 (io), 36 P0.1/AD1 (io), 37 P0.0/AD0 (io), 38 VCC (power), 39 NIC, 40 P1.0/T2 (io), 41 P1.1/T2EX (io), 42 P1.2/ECI (io), 43 P1.3/CEX0 (io), 44 P1.4/CEX1 (io)

## P87C54SBPN
designator U?
80C51 8-Bit Microcontroller Family: 256 B RAM, 16 kB OTP, 2.7V-5.5V, Low Power, High Speed
footprint SOT129-1 (DIP, Plastic; 40 Leads; Row Spacing 15.24 mm; Pitch 2.54 mm)
pins: 1 P1.0/T2 (io), 2 P1.1/T2EX (io), 3 P1.2/ECI (io), 4 P1.3/CEX0 (io), 5 P1.4/CEX1 (io), 6 P1.5/CEX2 (io), 7 P1.6/CEX3 (io), 8 P1.7/CEX4 (io), 9 RST (in), 10 P3.0/RxD (io), 11 P3.1/TxD (io), 12 P3.2/~{INT}0 (io), 13 P3.3/~{INT}1 (io), 14 P3.4/T0 (io), 15 P3.5/T1 (io), 16 P3.6/~{WR} (io), 17 P3.7/~{RD} (io), 18 XTAL2 (out), 19 XTAL1 (in), 20 VSS (power), 21 P2.0/A8 (io), 22 P2.1/A9 (io), 23 P2.2/A10 (io), 24 P2.3/A11 (io), 25 P2.4/A12 (io), 26 P2.5/A13 (io), 27 P2.6/A14 (io), 28 P2.7/A15 (io), 29 ~{PSEN} (out), 30 ALE/~{PROG} (io), 31 ~{EA}/VPP (in), 32 P0.7/AD7 (io), 33 P0.6/AD6 (io), 34 P0.5/AD5 (io), 35 P0.4/AD4 (io), 36 P0.3/AD3 (io), 37 P0.2/AD2 (io), 38 P0.1/AD1 (io), 39 P0.0/AD0 (io), 40 VCC (power)

## P87C54SFAA
designator U?
80C51 8-Bit Microcontroller Family: 256 B RAM, 16 kB OTP, 2.7V-5.5V, Low Power, High Speed
footprint SOT187-2_N (Leaded Chip Carrier, 44-Leads, Body 16.6x16.6mm, Pitch 1.27mm, IPC Medium Density)
footprint SOT187-2_L (Leaded Chip Carrier, 44-Leads, Body 16.6x16.6mm, Pitch 1.27mm, IPC High Density)
footprint SOT187-2_M (Leaded Chip Carrier, 44-Leads, Body 16.6x16.6mm, Pitch 1.27mm, IPC Low Density)
pins: 1 NIC, 2 P1.0/T2 (io), 3 P1.1/T2EX (io), 4 P1.2/ECI (io), 5 P1.3/CEX0 (io), 6 P1.4/CEX1 (io), 7 P1.5/CEX2 (io), 8 P1.6/CEX3 (io), 9 P1.7/CEX4 (io), 10 RST (in), 11 P3.0/RxD (io), 12 NIC, 13 P3.1/TxD (io), 14 P3.2/~{INT}0 (io), 15 P3.3/~{INT}1 (io), 16 P3.4/T0 (io), 17 P3.5/T1 (io), 18 P3.6/~{WR} (io), 19 P3.7/~{RD} (io), 20 XTAL2 (out), 21 XTAL1 (in), 22 VSS (power), 23 NIC, 24 P2.0/A8 (io), 25 P2.1/A9 (io), 26 P2.2/A10 (io), 27 P2.3/A11 (io), 28 P2.4/A12 (io), 29 P2.5/A13 (io), 30 P2.6/A14 (io), 31 P2.7/A15 (io), 32 ~{PSEN} (out), 33 ALE/~{PROG} (io), 34 NIC, 35 ~{EA}/VPP (in), 36 P0.7/AD7 (io), 37 P0.6/AD6 (io), 38 P0.5/AD5 (io), 39 P0.4/AD4 (io), 40 P0.3/AD3 (io), 41 P0.2/AD2 (io), 42 P0.1/AD1 (io), 43 P0.0/AD0 (io), 44 VCC (power)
